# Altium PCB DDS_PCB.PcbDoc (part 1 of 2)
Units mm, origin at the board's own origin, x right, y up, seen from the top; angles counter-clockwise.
Board outline 101.55 x 88.3 mm, 8 copper layers (TOP_L1, Plane_L2, Inner_L3, Plane_L4, Plane_L5, Inner_L6, Plane_L7, Bottom Layer_L8), stack 0.681 mm thick; 434 components, 266 nets, 1385 pads, 24 vias.
Unrouted connection lines stored in the file: 977.
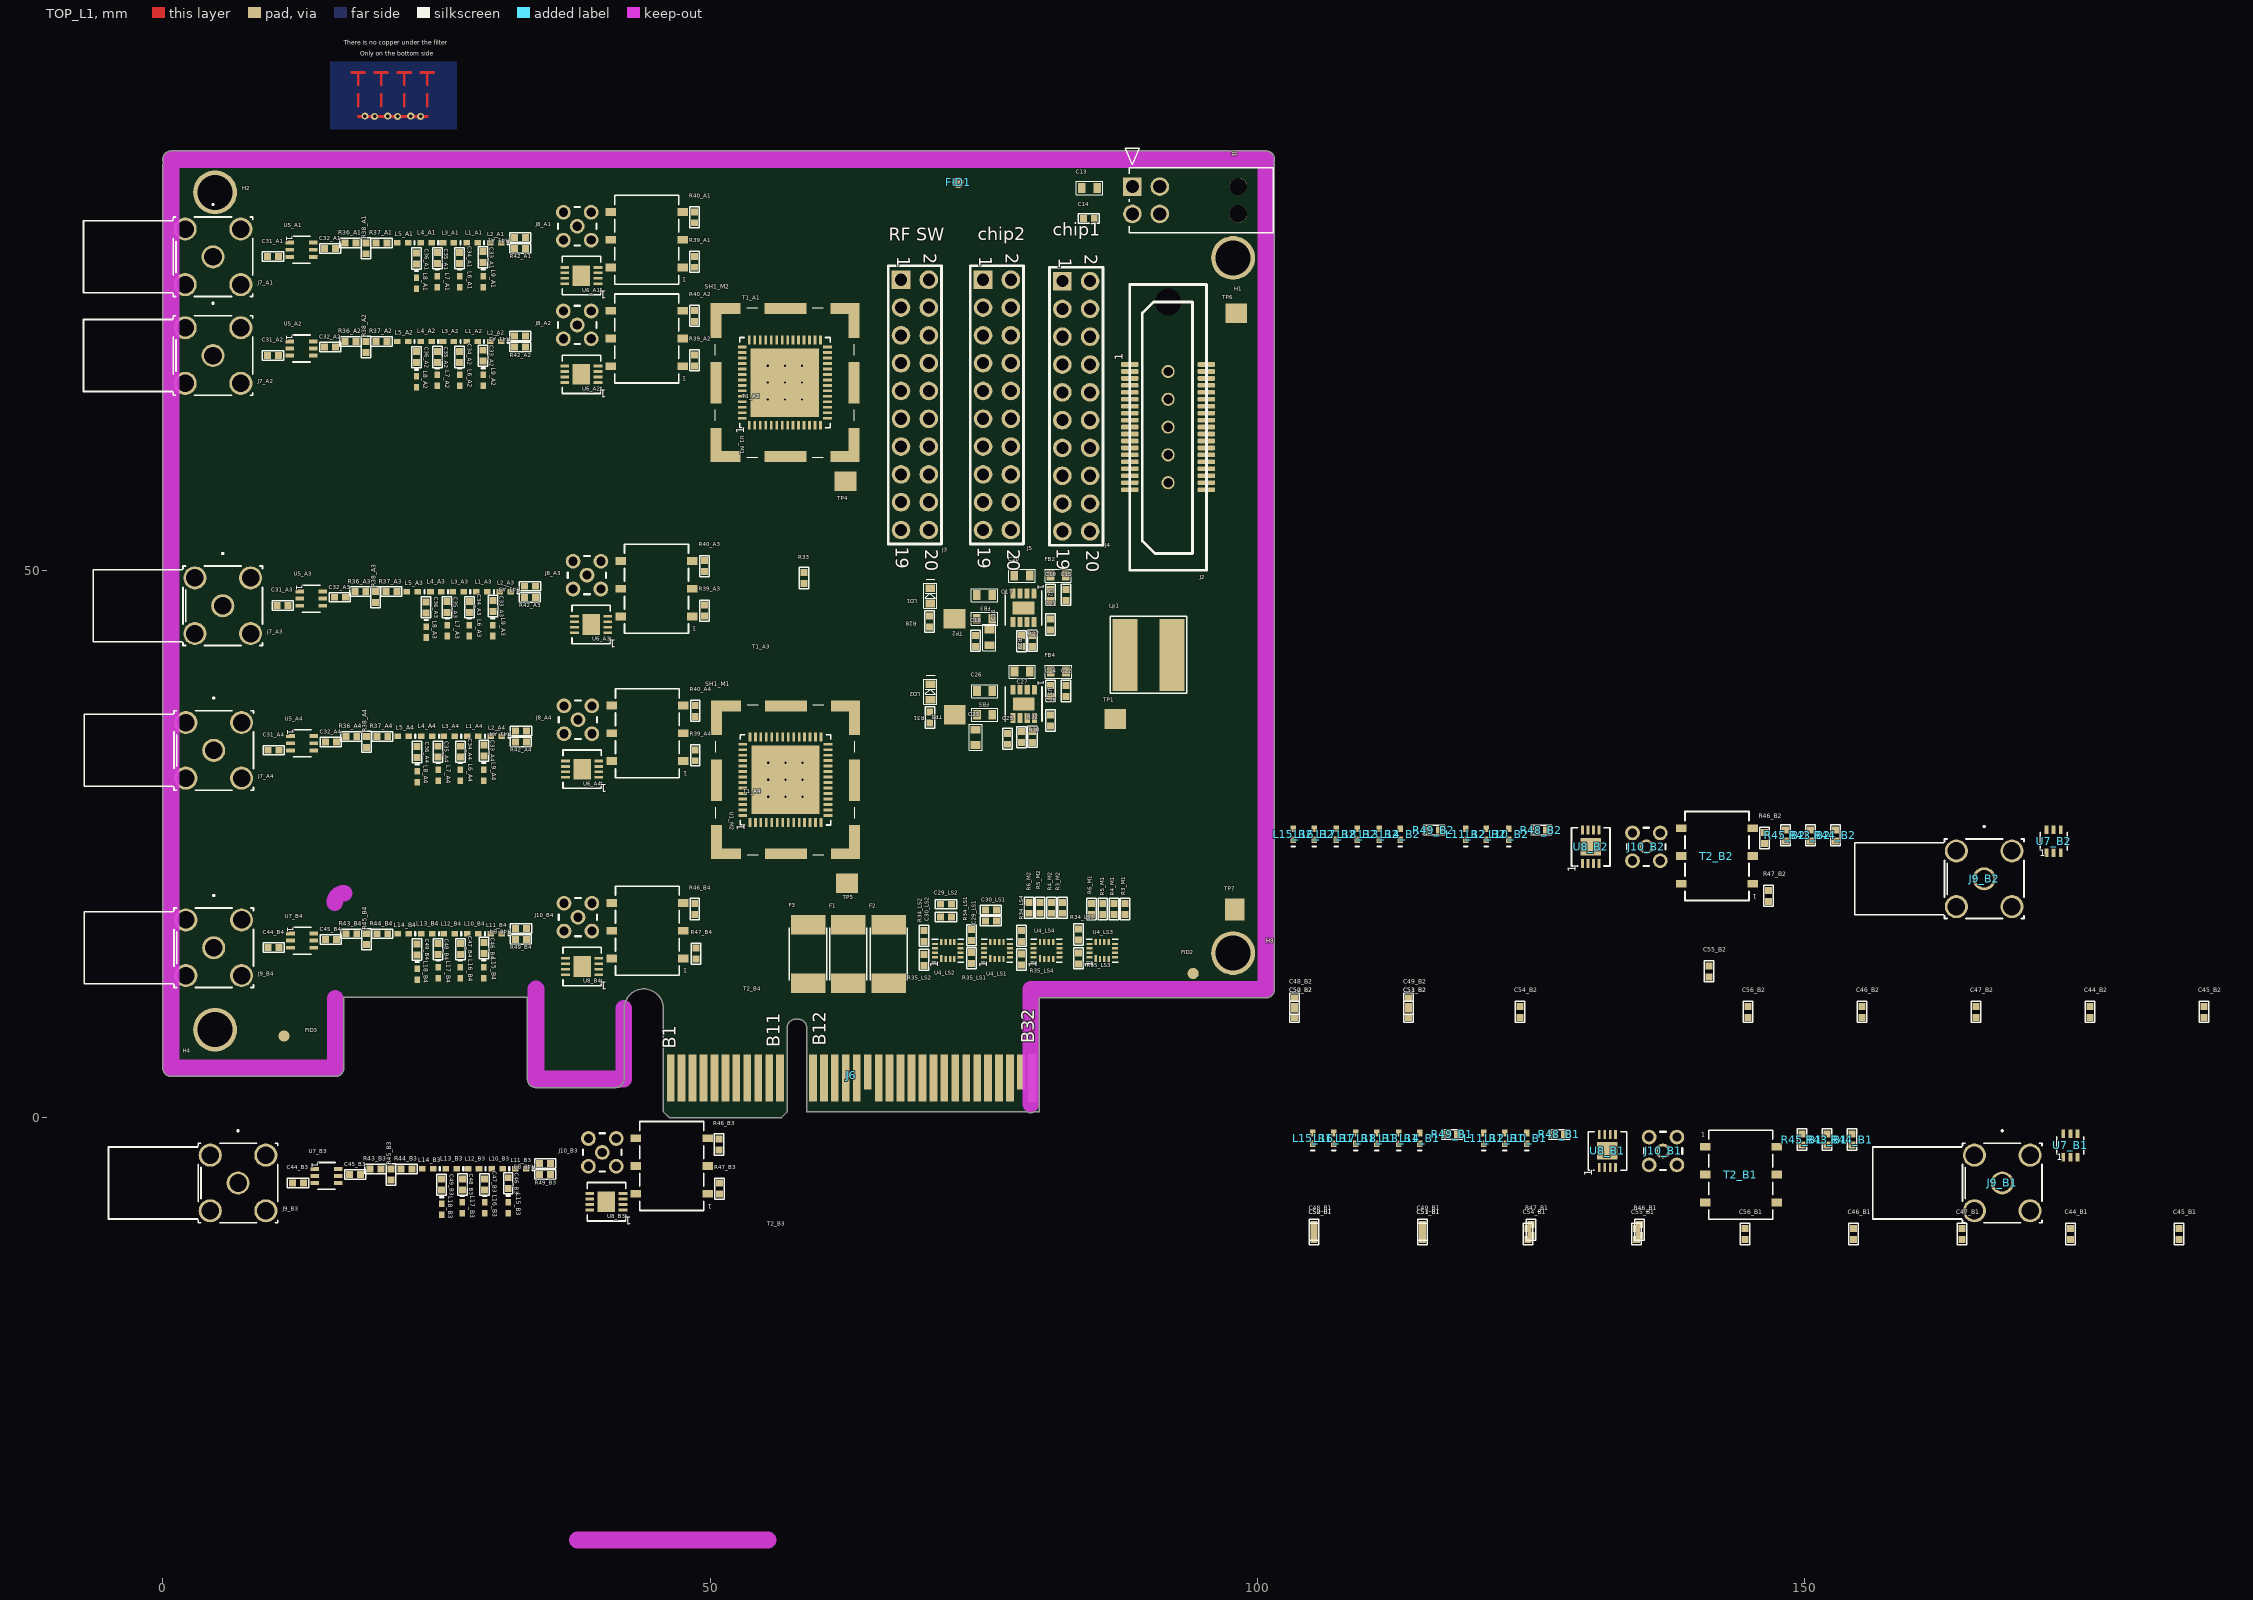
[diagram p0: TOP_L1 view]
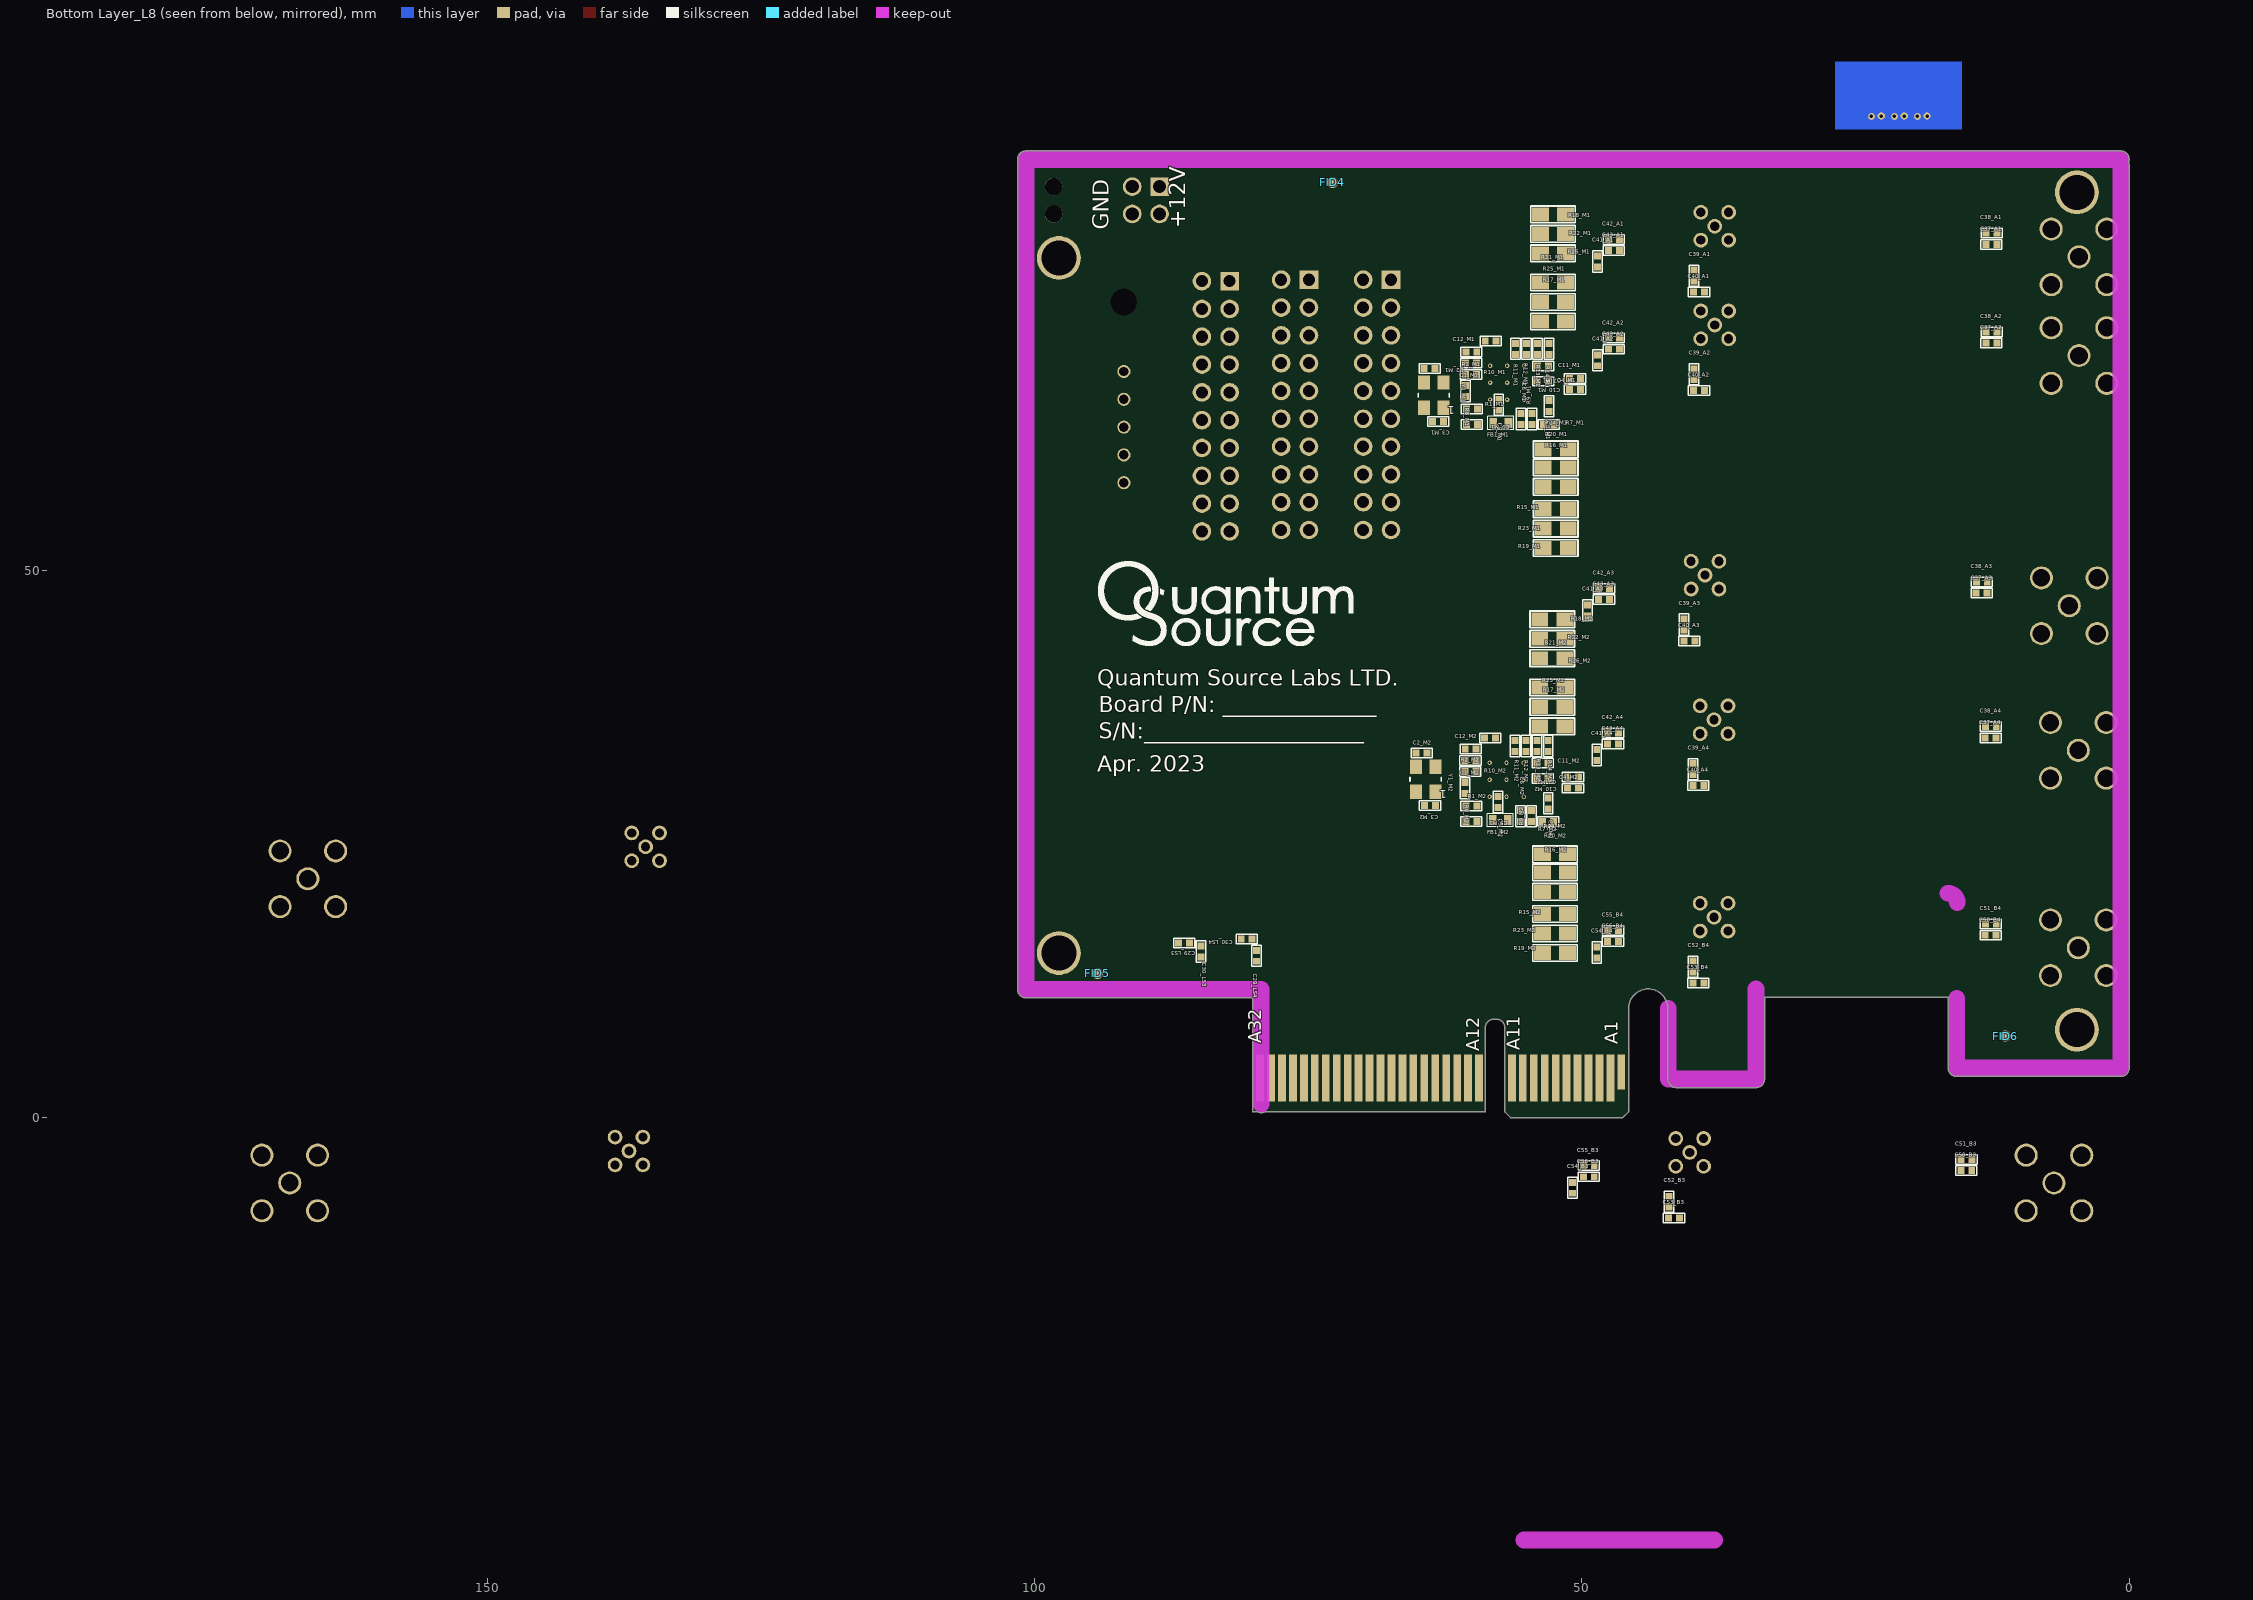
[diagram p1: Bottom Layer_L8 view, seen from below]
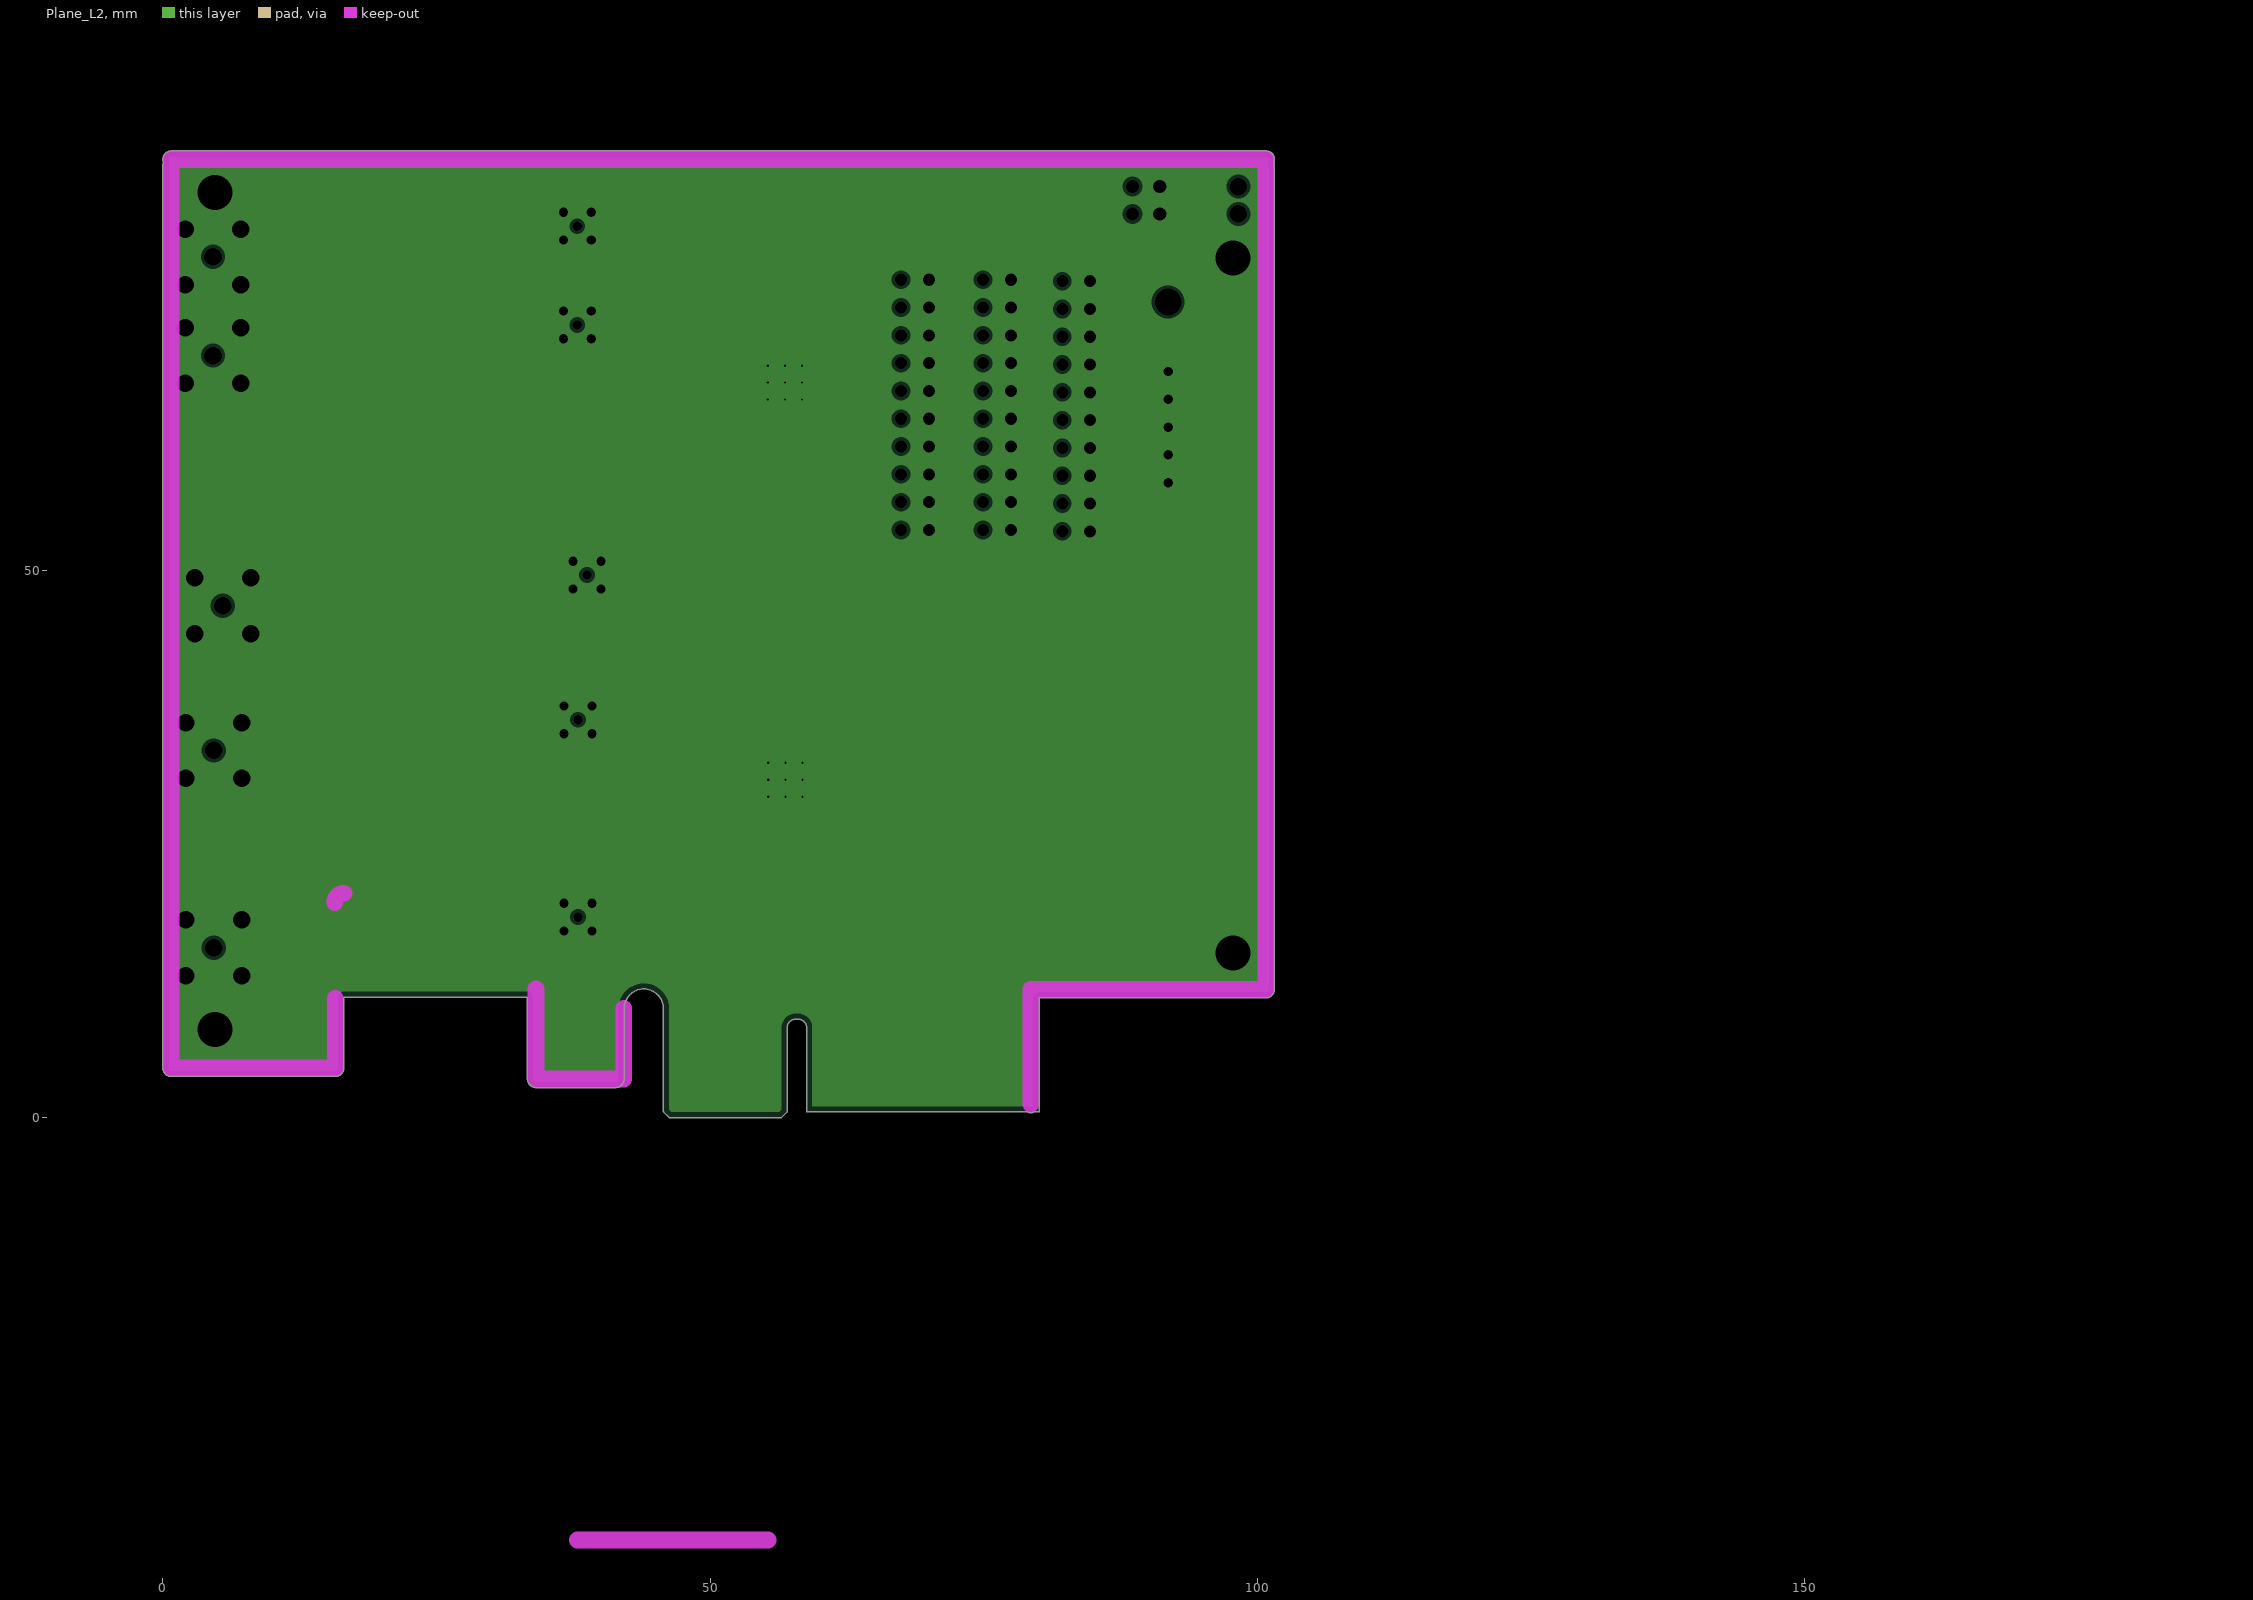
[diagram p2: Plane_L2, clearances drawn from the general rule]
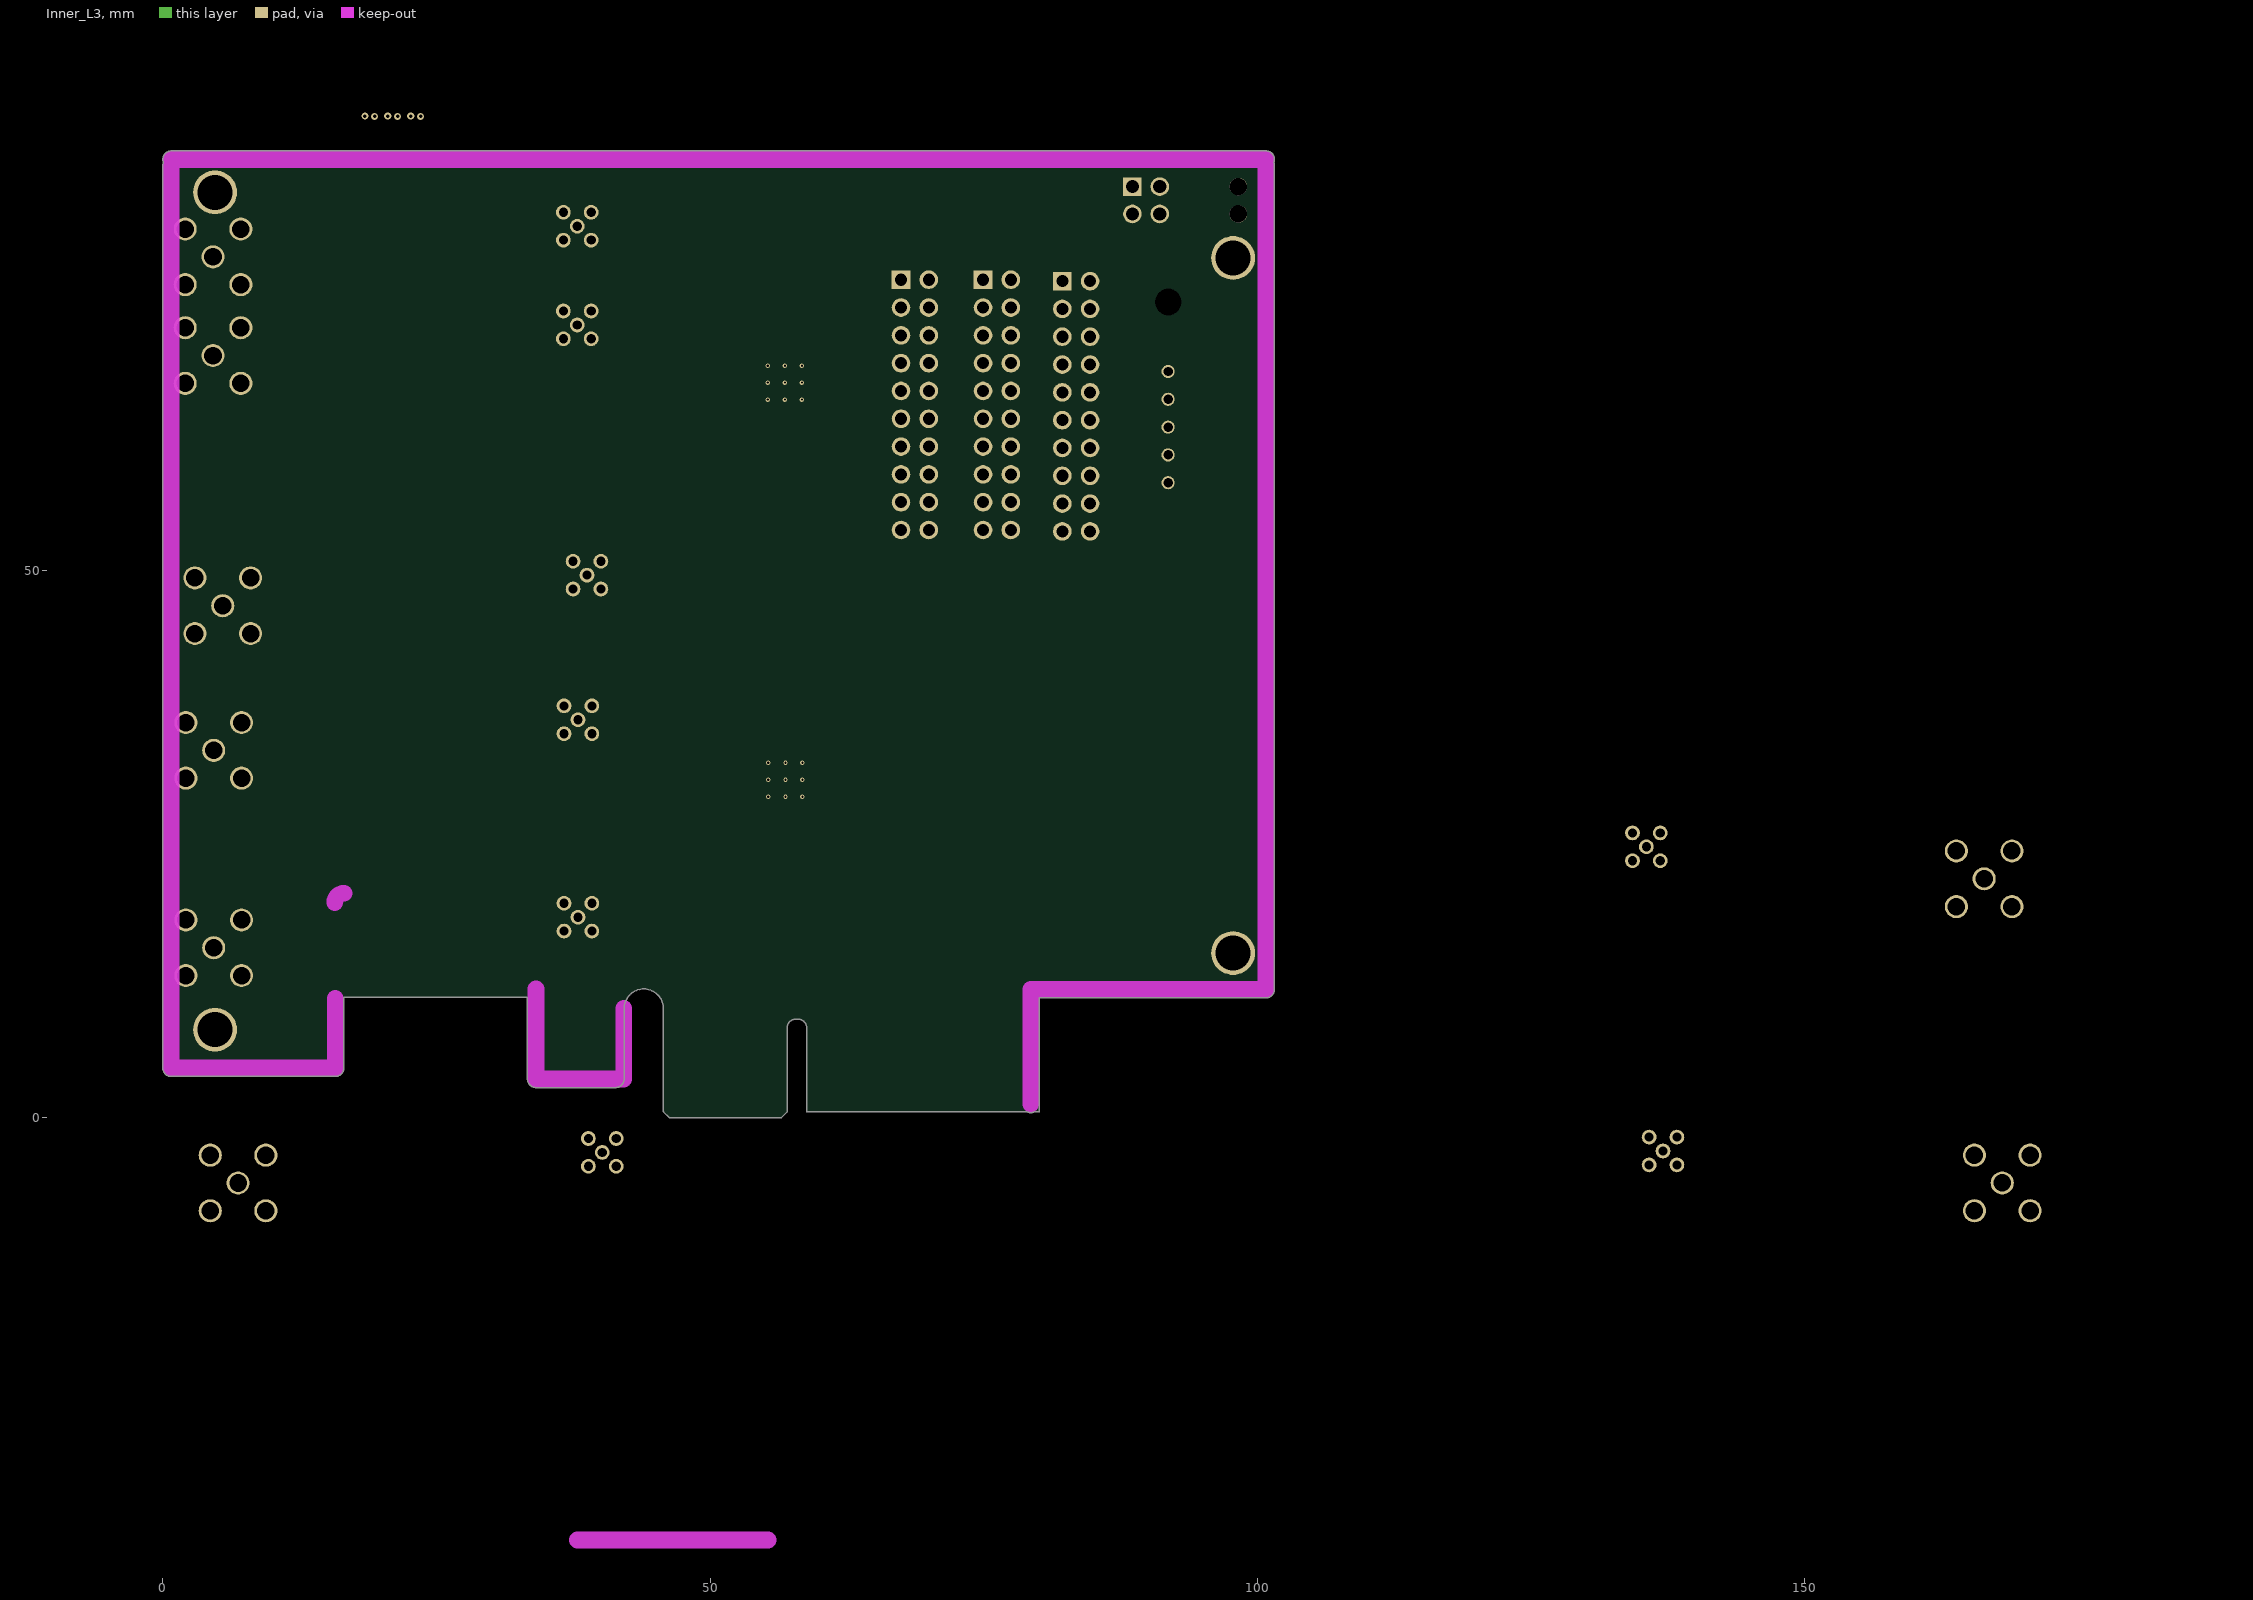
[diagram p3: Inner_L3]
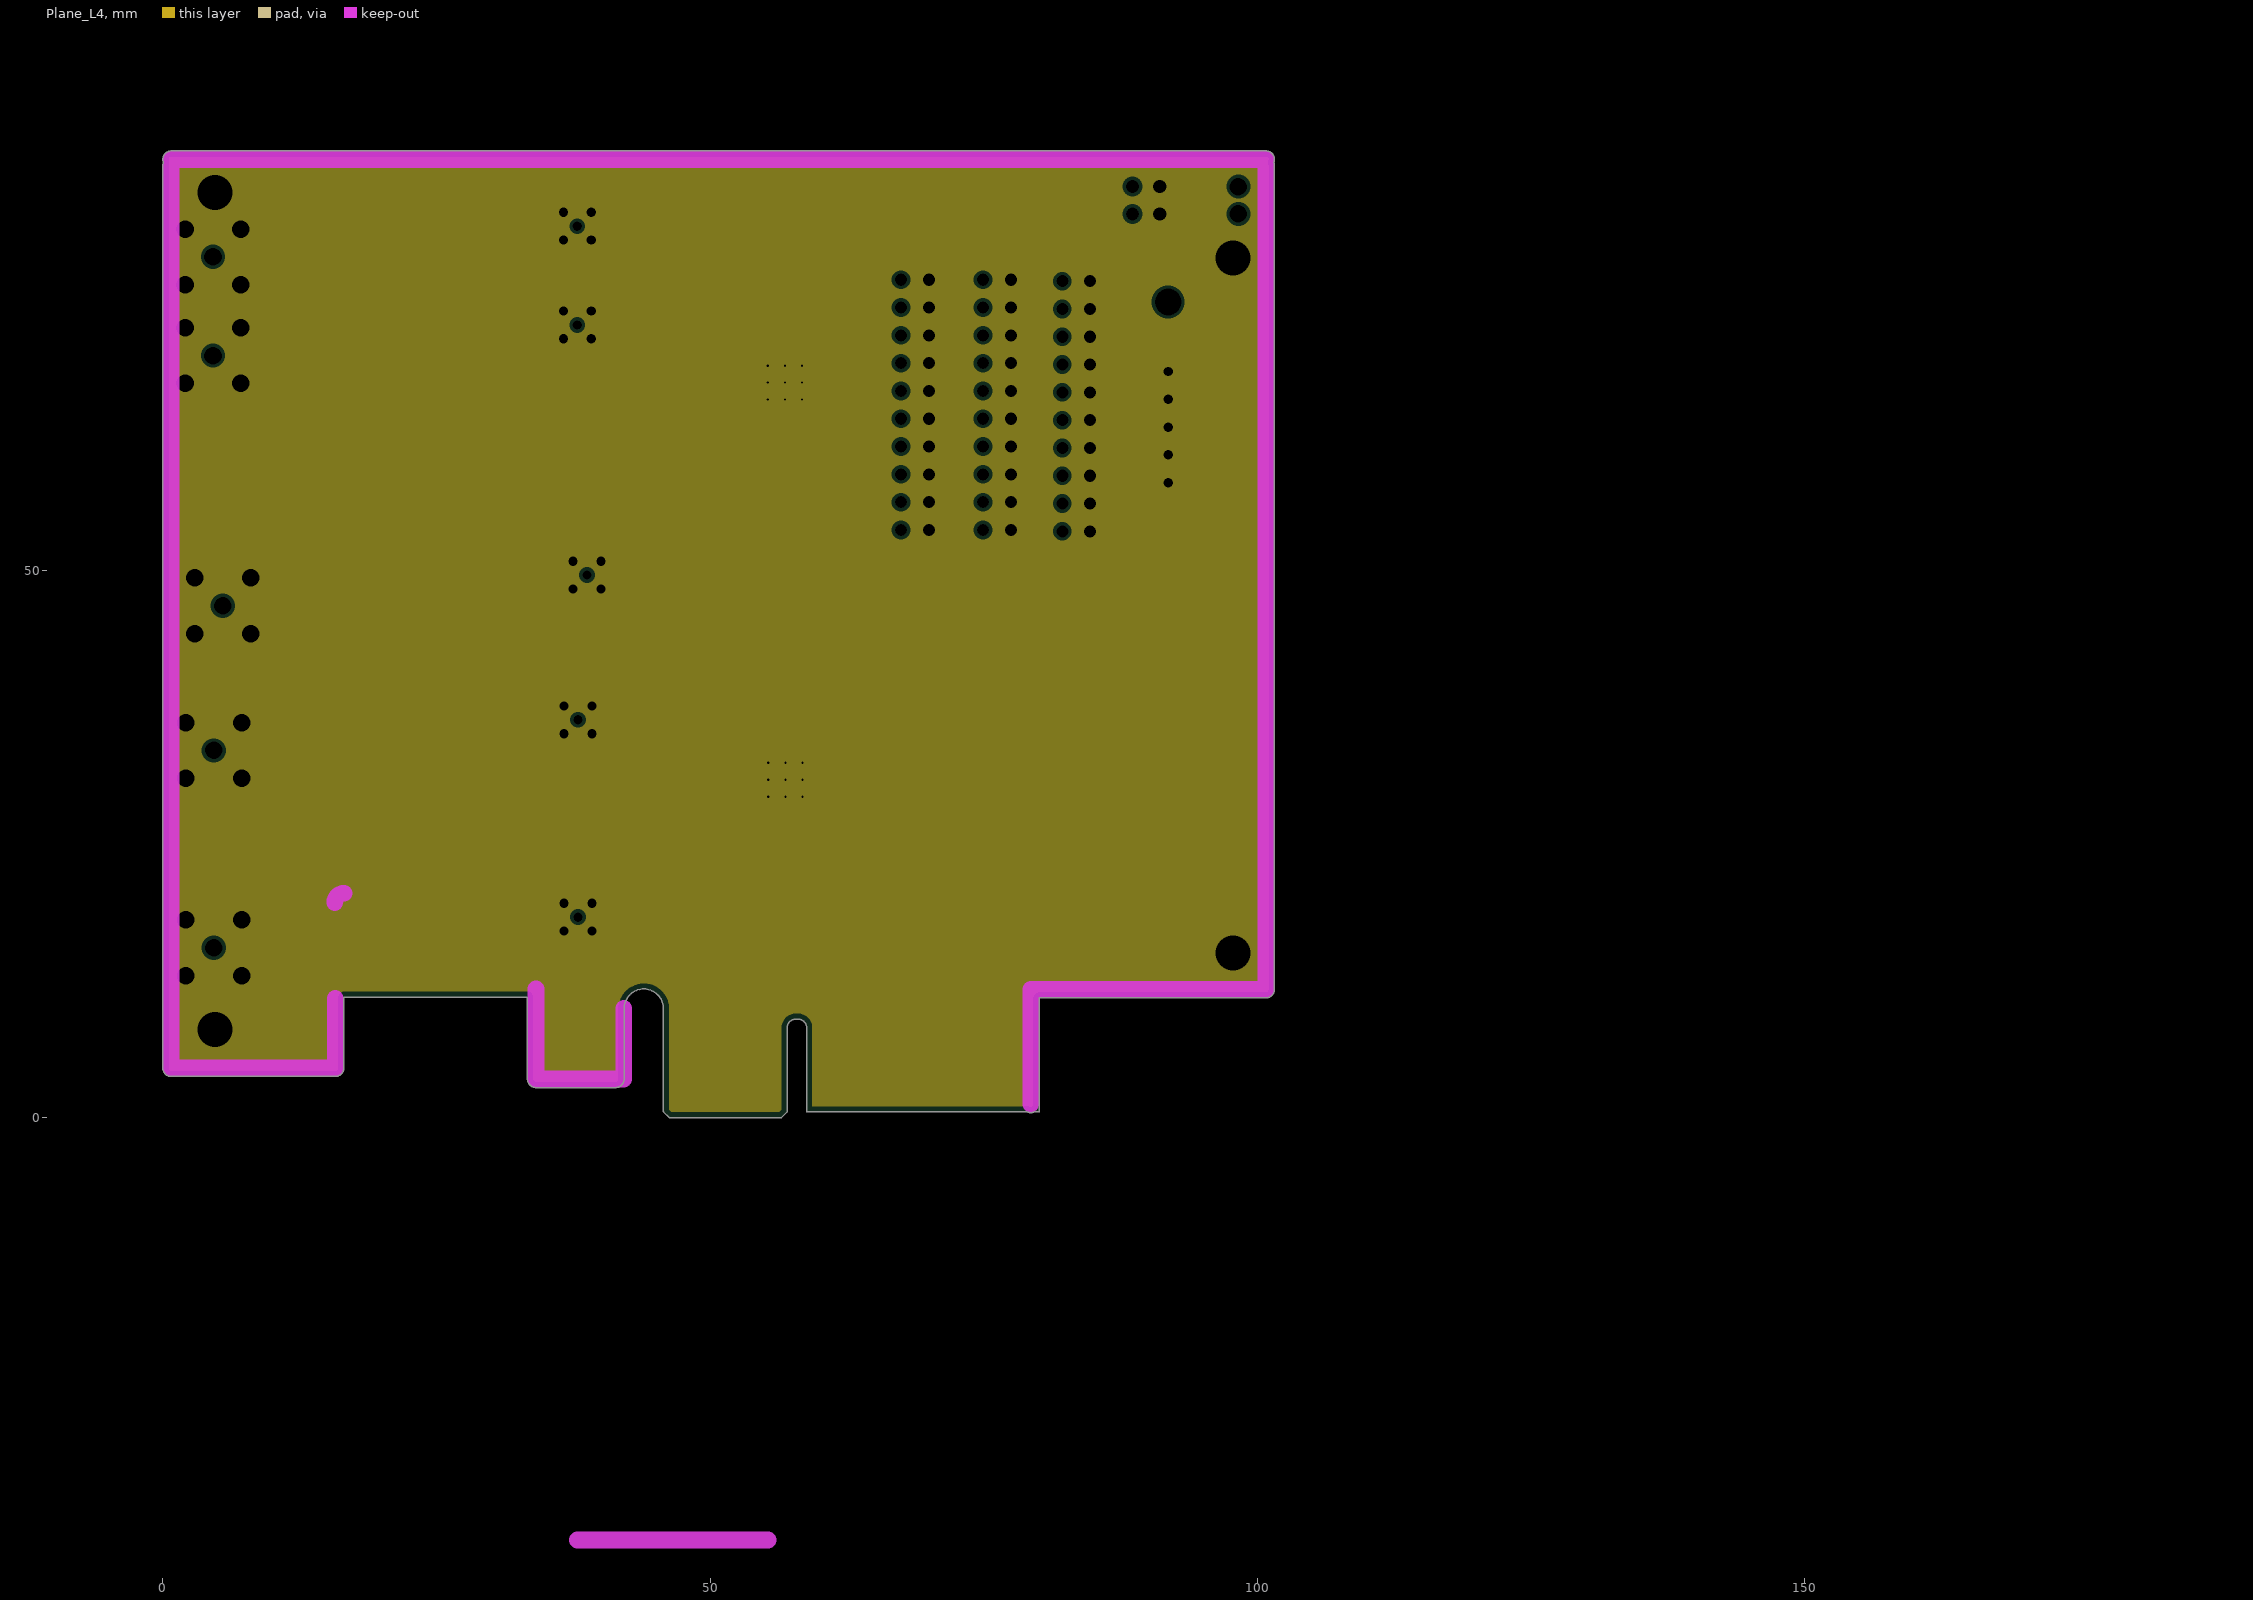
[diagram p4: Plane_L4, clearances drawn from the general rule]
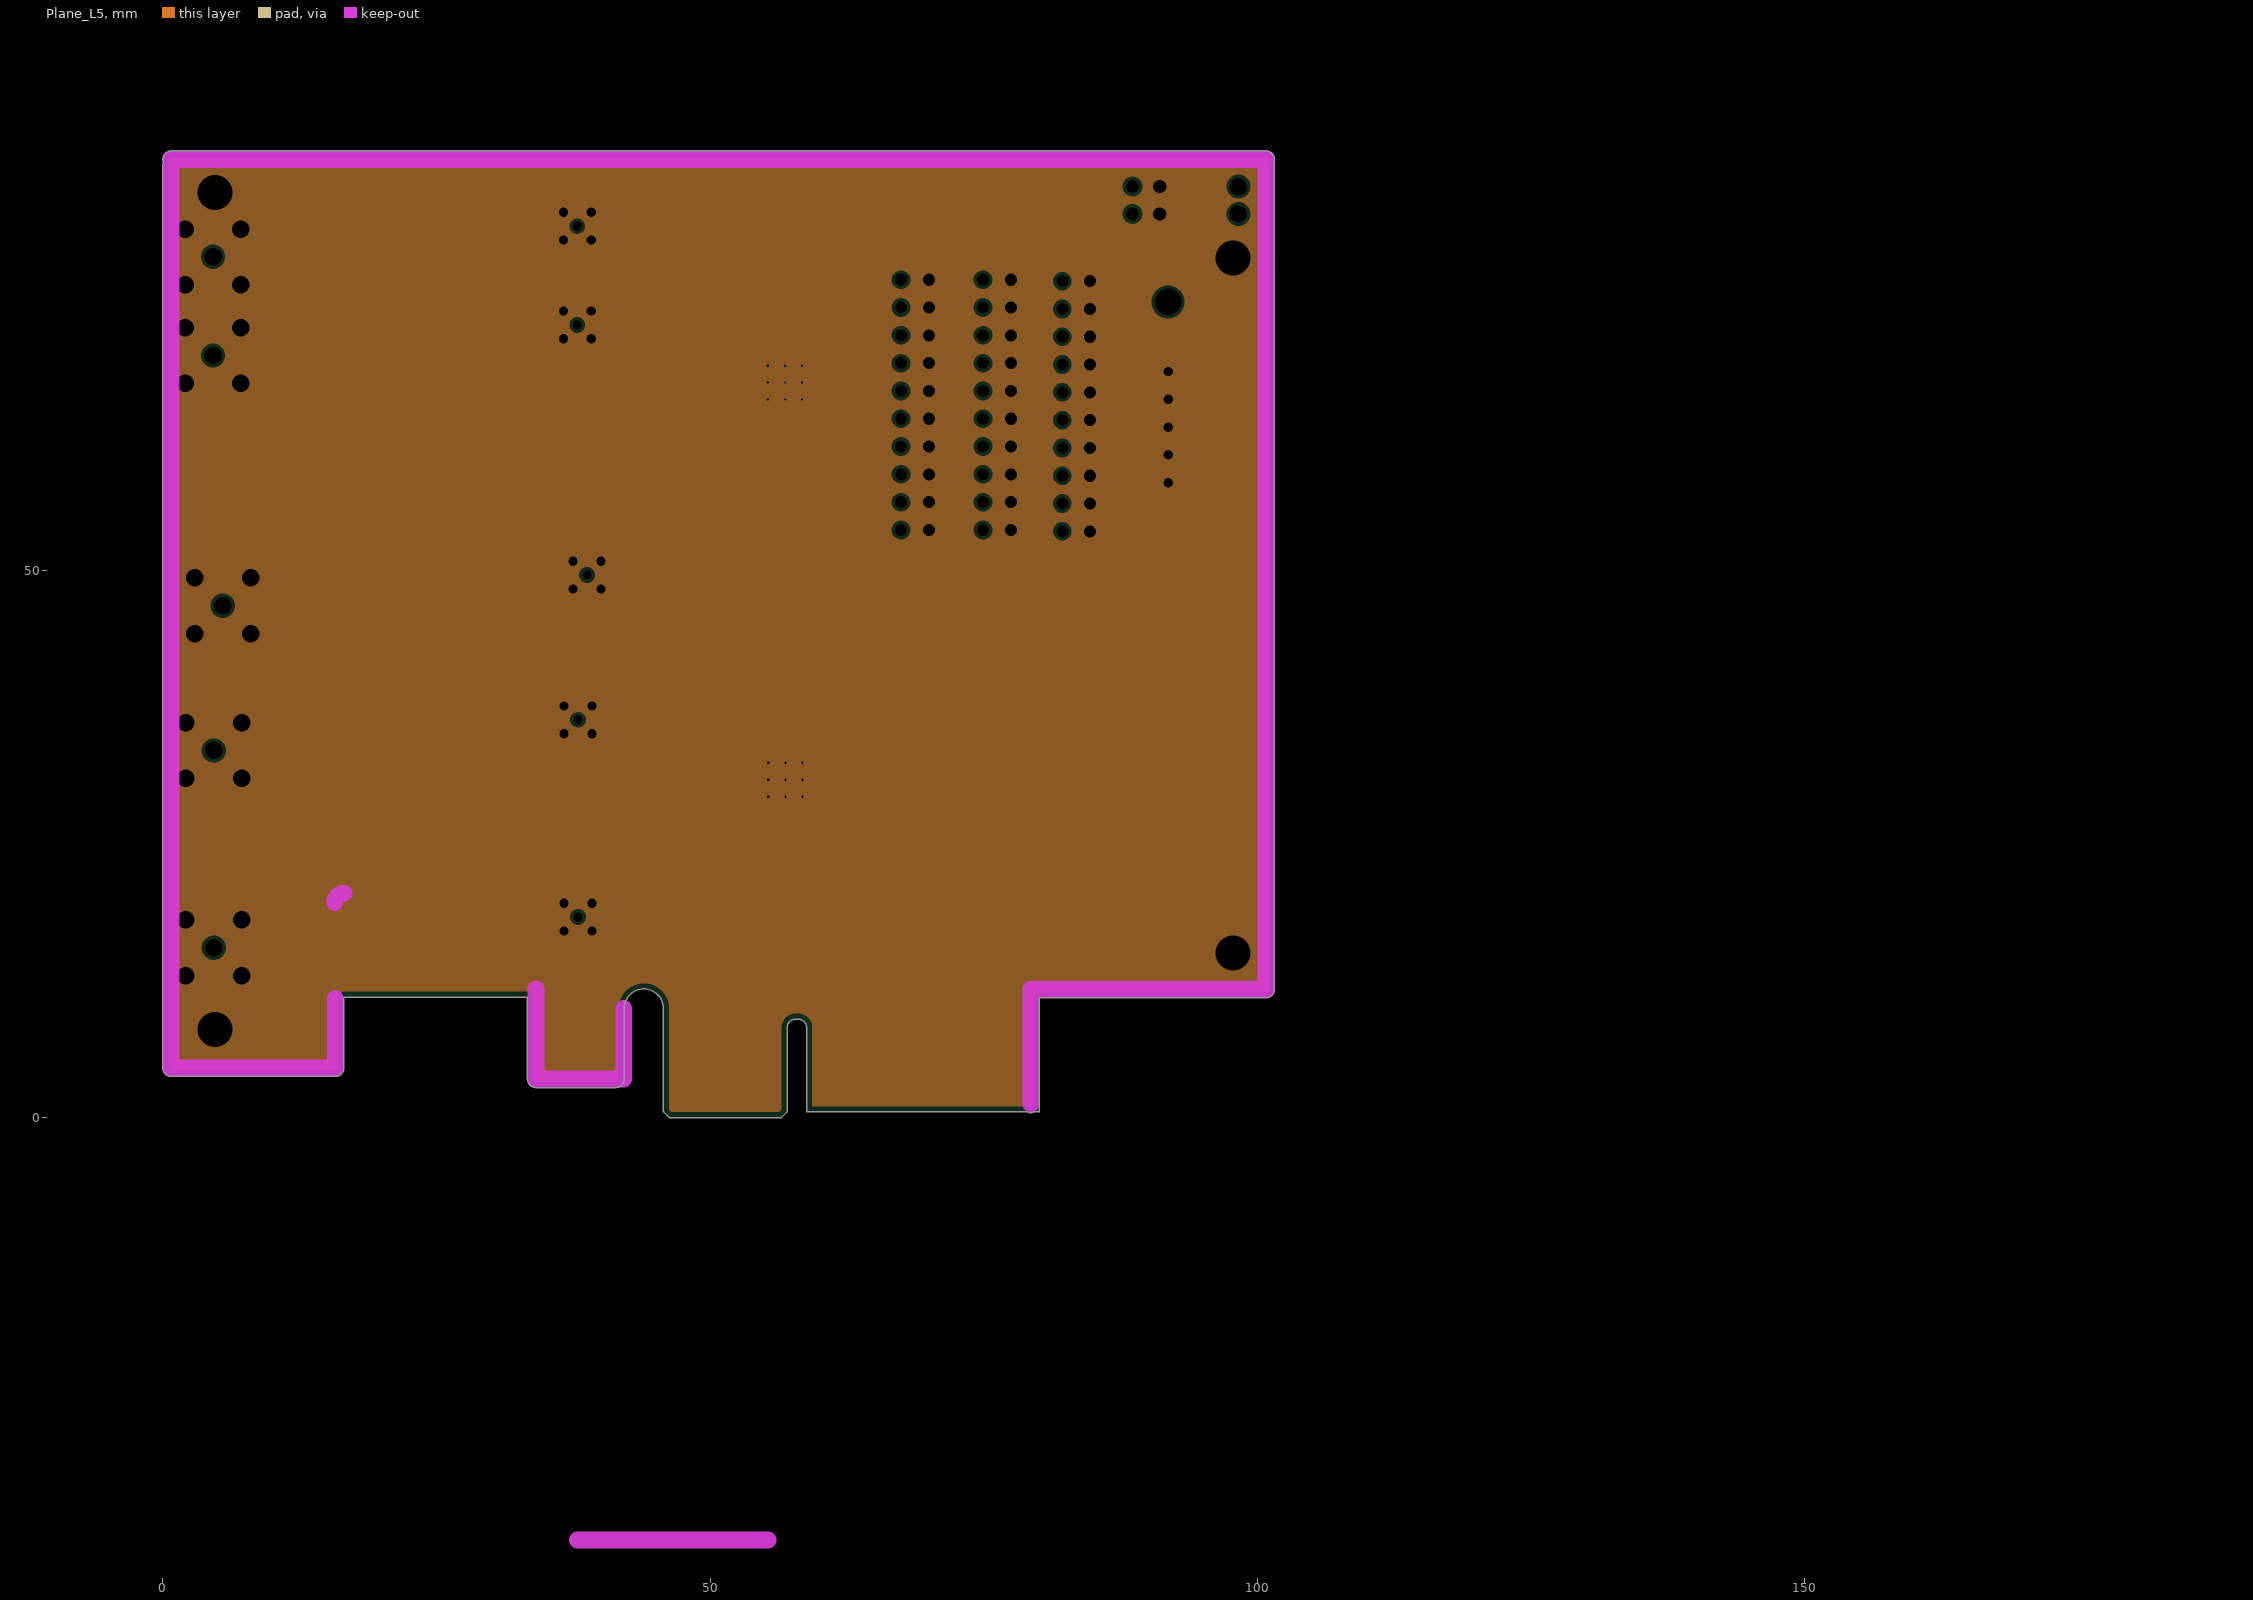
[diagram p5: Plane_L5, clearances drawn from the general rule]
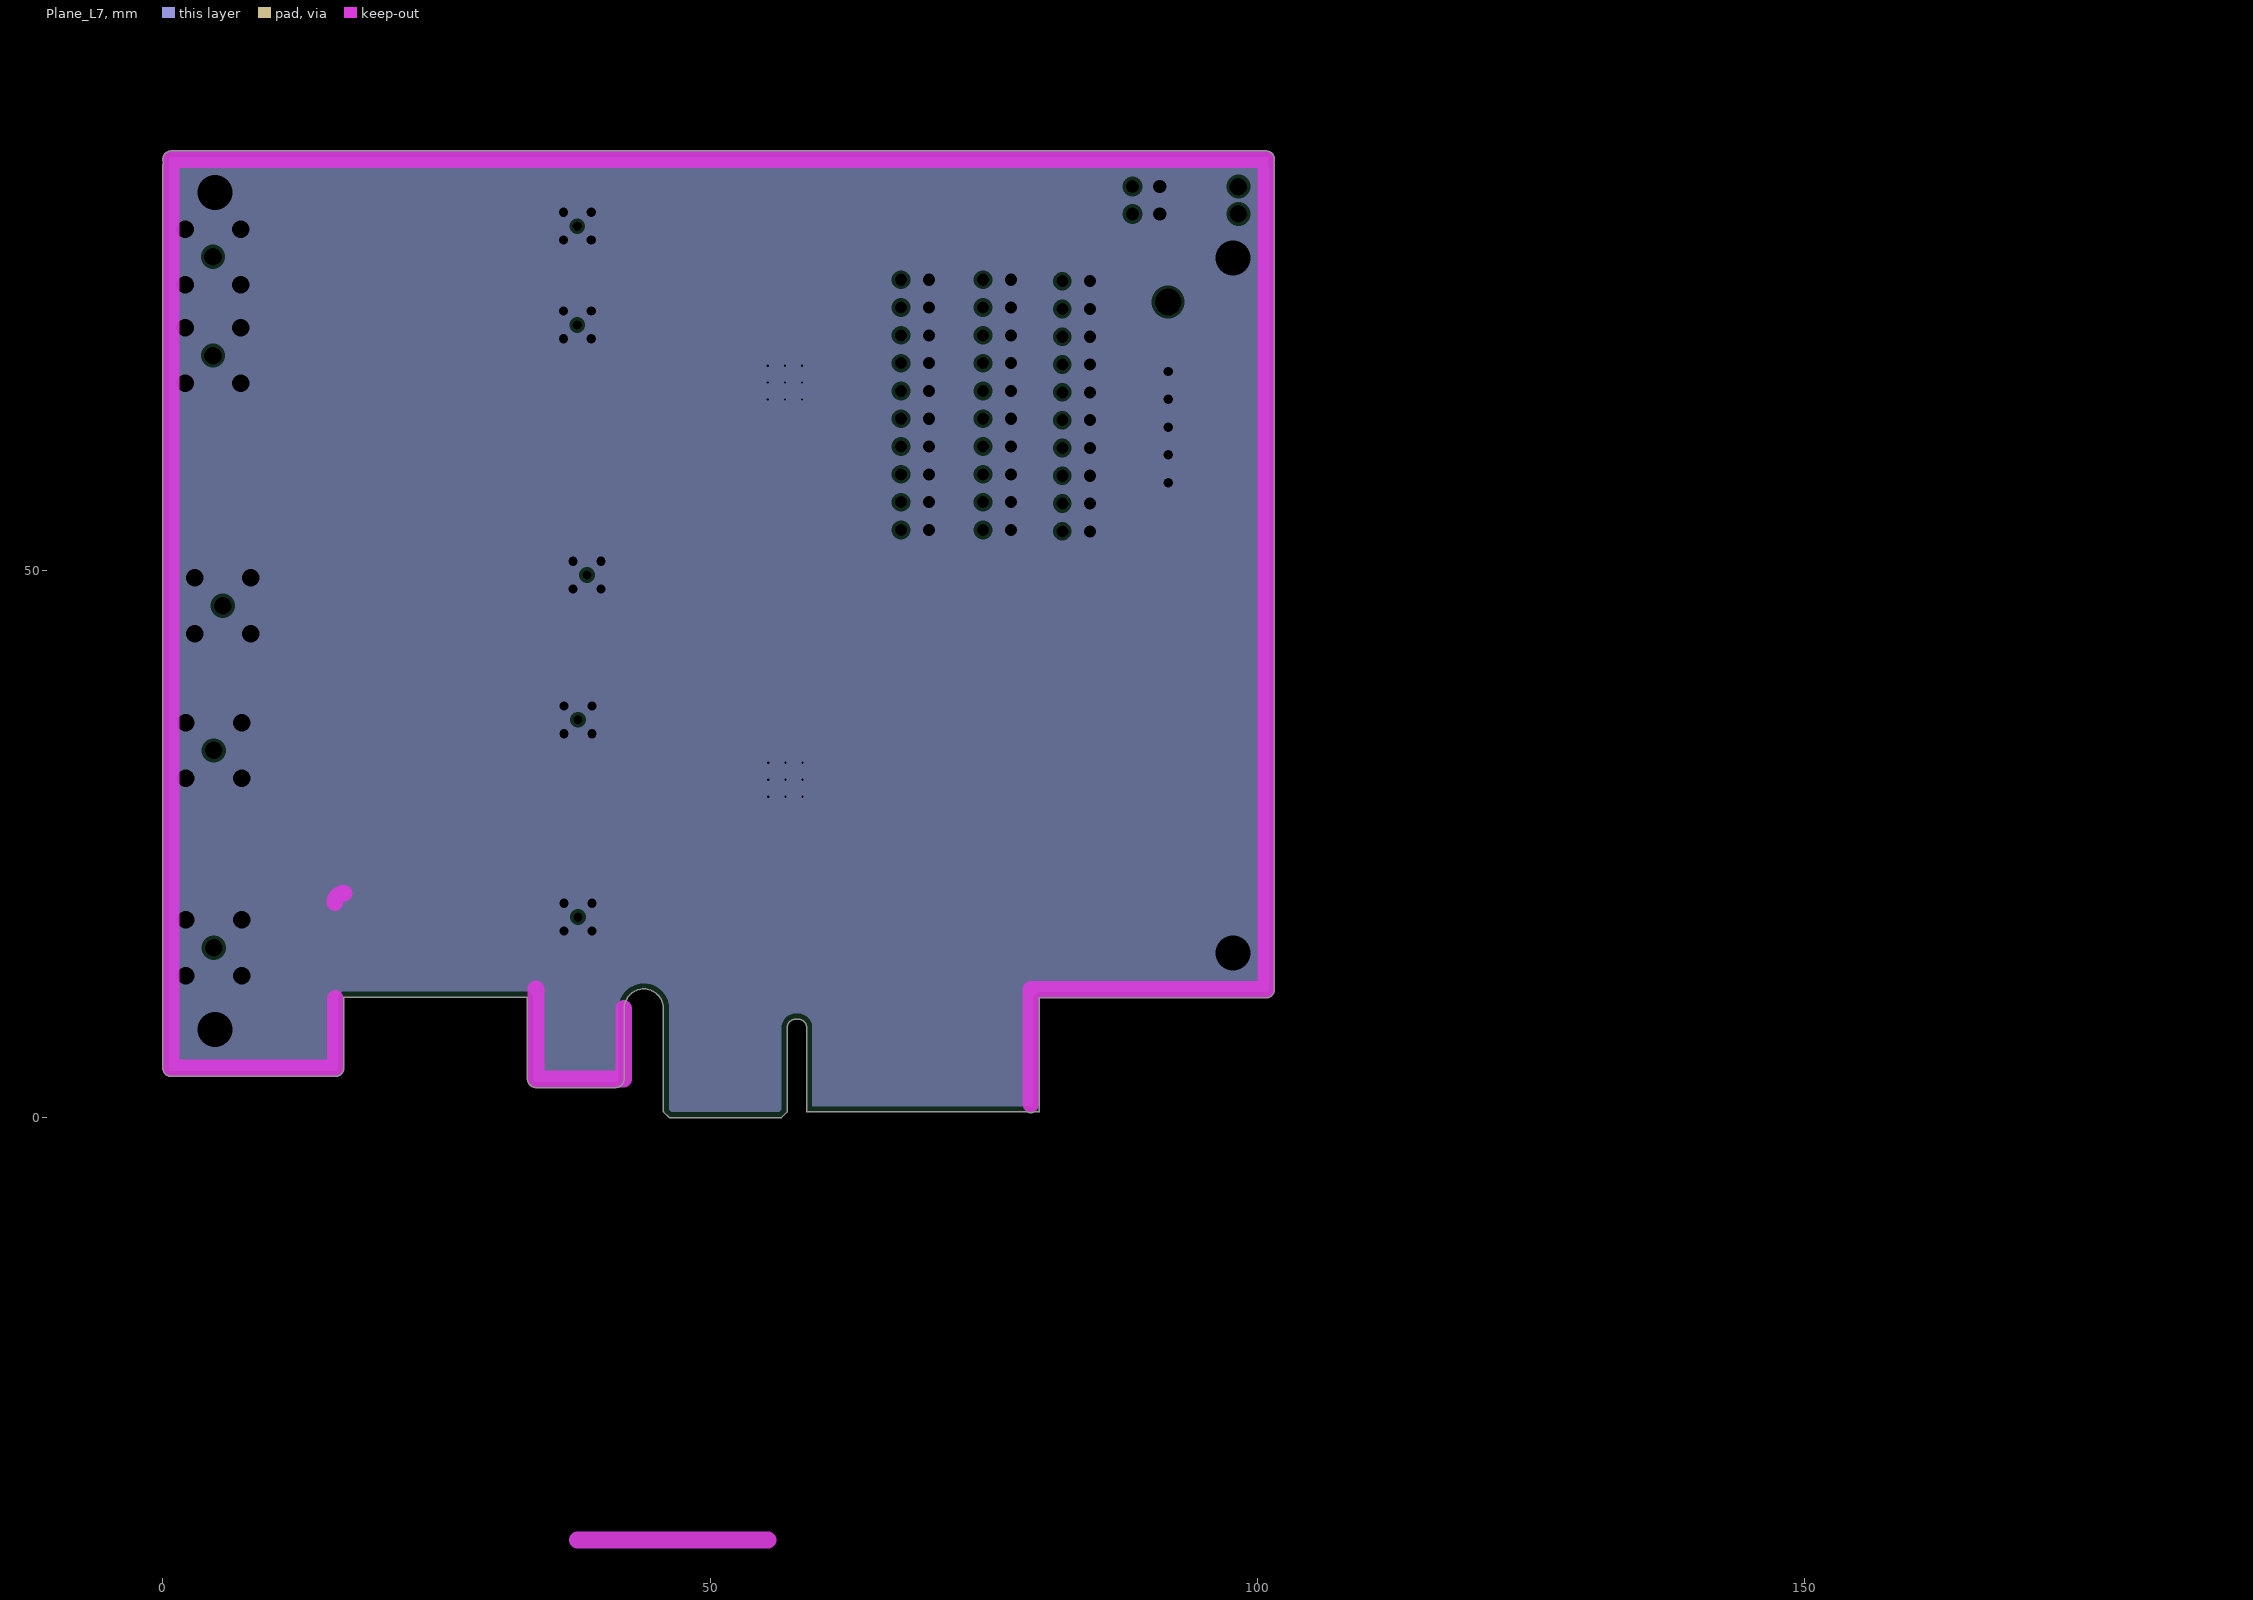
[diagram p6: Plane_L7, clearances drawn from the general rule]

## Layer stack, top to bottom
Top Solder: solder mask 0.0102, Solder Resist, Dk 3.5
TOP_L1: signal copper 0.0152
Dielectric1: core 0.0737, FR-4, Dk 3.2
Plane_L2: plane copper 0.0178, net GND
Dielectric7: prepreg 0.0762, FR-4, Dk 3.3
Inner_L3: signal copper 0.0178
Dielectric4: core 0.0711, FR-4, Dk 3.1
Plane_L4: plane copper 0.0305, net GND
Dielectric10: prepreg 0.0762, FR-4, Dk 3.3
Plane_L5: plane copper 0.0305, net GND
Dielectric 1: core 0.0711, FR-4, Dk 3.1
Inner_L6: signal copper 0.0178
Dielectric 6: prepreg 0.0762, FR-4, Dk 3.3
Plane_L7: plane copper 0.0178, net GND
Dielectric 7: core 0.0737, FR-4, Dk 3.2
Bottom Layer_L8: signal copper 0.0152
Board Layer Stack Bottom Solder: solder mask 0.0102, Solder Resist, Dk 3.5

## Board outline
0.762,3.734 cw(c0.762,4.509) -0.013,4.509 -0.013,86.932 cw(c0.762,86.932) 0.043,87.221 cw(c0.762,87.509) 0.762,88.285 100.762,88.285 cw(c100.762,87.509) 101.538,87.509 cw(c100.762,87.509) 101.482,87.221 cw(c100.762,86.932) 101.538,86.933 101.538,86.932 101.538,11.694 cw(c100.762,11.694) 100.762,10.919 80.053,10.919 80.053,0.522 80.026,0.496 79.569,0.496 cw(c79.264,1.209) 78.96,0.496 58.826,0.496 58.8,0.522 58.8,8.187 ccw(c58.009,8.187) 58.009,8.978 57.815,8.978 ccw(c57.815,8.183) 57.021,8.183 57.021,0.513 57.013,0.495 56.509,-0.009 56.491,-0.017 46.262,-0.017 46.244,-0.009 45.737,0.492 45.723,0.517 45.723,9.937 ccw(c43.927,9.937) 43.927,11.734 43.926,11.734 ccw(c43.926,9.959) 42.309,10.69 42.292,10.683 ccw(c43.926,9.937) 42.13,9.937 42.13,3.514 42.13,3.512 cw(c41.342,3.512) 41.342,2.724 34.087,2.724 cw(c34.087,3.512) 33.298,3.512 33.298,10.974 16.526,10.974 16.526,4.522 cw(c15.737,4.522) 15.737,3.734

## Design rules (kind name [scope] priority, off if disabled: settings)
Clearance [All] p1: gap=0.203 ignorepadtopadclearanceinfootprint=FALSE except(0: Arc-Hole Track-Hole SMDPad-Hole THPad-Hole Via-Hole Fill-Hole Poly-Hole Region-Hole Text-Hole)
DiffPairsRouting DiffPair_100OhmDiffPairsRouting [InDifferentialPairClass('New Class_100Ohm')] p1: maxlimit=0.165 minlimit=0.152 mostfreqgap=0.165 toplayer_maxgap=0.152 toplayer_prefgap=0.152 toplayer_minwidth=0.381 toplayer_maxwidth=0.381 toplayer_prefwidth=0.381 midlayer2_mingap=0.165 midlayer2_minwidth=0.381 midlayer2_maxwidth=0.381 midlayer2_prefwidth=0.381 midlayer4_mingap=0.165 midlayer4_minwidth=0.381 midlayer4_maxwidth=0.381 midlayer4_prefwidth=0.381 bottomlayer_maxgap=0.152 bottomlayer_prefgap=0.152 bottomlayer_minwidth=0.381 bottomlayer_maxwidth=0.381 bottomlayer_prefwidth=0.381 maxuncoupledlength=12.7
Length Length_GPIO2_[0..15] [InNetClass('GPIO2_[0..15]')] p1: maxlimit=41.351 minlimit=40.64
Length Length_DDR3_A0-15_control [InNetClass('DDR3_A[0..15]_CONTROL')] p2: maxlimit=60.985 minlimit=60.96
Length Length_SSF_TD1-6 [InDifferentialPairClass('New Class_SSF_TD1-6')] p3: maxlimit=268.707 minlimit=268.681
Length Length_PCI_RX0-7 [InDifferentialPairClass('New Class_PCI_RX0-6')] p4: maxlimit=66.065 minlimit=66.04
Length Length_PCI_TX0-7 [InDifferentialPairClass('New Class_PCI_TX0-6')] p5: maxlimit=51.206 minlimit=51.181
MatchedLengths DiffPair_85OhmMatchedLengths [All] p1: tolerance=0.635 checknetsindiffpair=TRUE checkdiffpairvsdiffpair=FALSE checkxsignals=FALSE checkothers=FALSE
MatchedLengths DiffPair_80OhmMatchedLengths [All] p2: tolerance=0.635 checknetsindiffpair=TRUE checkdiffpairvsdiffpair=FALSE checkxsignals=FALSE checkothers=FALSE
MatchedLengths DiffPair_100OhmMatchedLengths [All] p3: tolerance=0.635 checknetsindiffpair=TRUE checkdiffpairvsdiffpair=FALSE checkxsignals=FALSE checkothers=FALSE
PlaneClearance [All] p1: clearance=0.305
PlaneConnect PlaneConnect_Via [Isvia] p1: planeconnectstyle=Direct reliefexpansion=0.508 reliefentries=4 reliefconductorwidth=0.254 reliefairgap=0.254
PlaneConnect [All] p2: planeconnectstyle=Relief reliefexpansion=0.508 reliefentries=4 reliefconductorwidth=0.508 reliefairgap=0.203
PolygonConnect PolygonConnect_1PWRPAD [InPadClass('New Class_PWRpad')] p1: connectstyle=Direct reliefconductorwidth=0.254 reliefentries=4 polygonreliefangle="90 Angle" airgapwidth=0.254
PolygonConnect PolygonConnect_PWR [InComponentClass('New Class_pwr')] p2: connectstyle=Relief reliefconductorwidth=0.762 reliefentries=4 polygonreliefangle="90 Angle" airgapwidth=0.254
PolygonConnect PolygonConnect_Via [Isvia] p3: connectstyle=Direct reliefconductorwidth=0.254 reliefentries=4 polygonreliefangle="90 Angle" airgapwidth=0.254
PolygonConnect PolygonConnect_TPs [InComponentClass('New Class_TPs')] p4: connectstyle=Direct reliefconductorwidth=0.254 reliefentries=4 polygonreliefangle="90 Angle" airgapwidth=0.254
PolygonConnect [All] p5: connectstyle=Relief reliefconductorwidth=0.508 reliefentries=4 polygonreliefangle="90 Angle" airgapwidth=0.254
RoomDefinition A4 [InComponentClass('A4')] p1: confinementstyle=ConfineIn formatcopy=TRUE lockcomponents=FALSE outline -7.62,29.16 49.403,29.16 49.403,39.574 -7.62,39.574
RoomDefinition B3 [InComponentClass('B3')] p2: confinementstyle=ConfineIn formatcopy=TRUE lockcomponents=FALSE outline -5.397,-10.363 51.626,-10.363 51.626,0.051 -5.397,0.051
RoomDefinition A1 [InComponentClass('A1')] p3: confinementstyle=ConfineIn formatcopy=TRUE lockcomponents=FALSE outline -7.62,74.245 49.403,74.245 49.403,84.659 -7.62,84.659
RoomDefinition A2 [InComponentClass('A2')] p4: confinementstyle=ConfineIn formatcopy=TRUE lockcomponents=FALSE outline -7.62,65.228 49.403,65.228 49.403,75.642 -7.62,75.642
RoomDefinition B4 [InComponentClass('B4')] p5: confinementstyle=ConfineIn formatcopy=TRUE lockcomponents=FALSE outline -7.62,11.126 49.53,11.126 49.53,21.54 -7.62,21.54
RoomDefinition B1 [InComponentClass('B1')] p6: confinementstyle=ConfineIn formatcopy=TRUE lockcomponents=FALSE outline 104.394,-10.056 175.895,-10.056 175.895,-0.658 104.394,-0.658
RoomDefinition A3 [InComponentClass('A3')] p7: confinementstyle=ConfineIn formatcopy=TRUE lockcomponents=FALSE outline -6.731,42.652 50.292,42.652 50.292,52.812 -6.731,52.812
RoomDefinition B2 [InComponentClass('B2')] p8: confinementstyle=ConfineIn formatcopy=TRUE lockcomponents=FALSE outline -7.62,65.228 49.403,65.228 49.403,75.642 -7.62,75.642
RoutingVias [All] p1: holewidth=0.254 width=0.508 viastyle="Through Hole" minholewidth=0.254 minwidth=0.508 maxholewidth=0.711 maxwidth=1.27
SilkToSolderMaskClearance SilkscreenOverComponentPads [IsPad] p1: minsilkscreentomaskgap=0.254 clearancetoexposedcopper=TRUE
SolderMaskExpansion [All] p1: expansion=0.102 istentingtop=FALSE
Width [All] p1: maxlimit=2.54 minlimit=0.152 preferedwidth=0.203
26 further rules are at their usual default settings.

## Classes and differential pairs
component class B4: C44_B4 C45_B4 C46_B4 C47_B4 C48_B4 C49_B4 C50_B4 C51_B4 C52_B4 C53_B4 C54_B4 C55_B4 C56_B4 J9_B4 J10_B4 L10_B4 L11_B4 L12_B4 L13_B4 L14_B4 L15_B4 L16_B4 L17_B4 L18_B4 R43_B4 R44_B4 R45_B4 R46_B4 R47_B4 R48_B4 R49_B4 T2_B4 U7_B4 U8_B4
component class B2: C44_B2 C45_B2 C46_B2 C47_B2 C48_B2 C49_B2 C50_B2 C51_B2 C52_B2 C53_B2 C54_B2 C55_B2 C56_B2 J9_B2 J10_B2 L10_B2 L11_B2 L12_B2 L13_B2 L14_B2 L15_B2 L16_B2 L17_B2 L18_B2 R43_B2 R44_B2 R45_B2 R46_B2 R47_B2 R48_B2 R49_B2 T2_B2 U7_B2 U8_B2
component class B1: C44_B1 C45_B1 C46_B1 C47_B1 C48_B1 C49_B1 C50_B1 C51_B1 C52_B1 C53_B1 C54_B1 C55_B1 C56_B1 J9_B1 J10_B1 L10_B1 L11_B1 L12_B1 L13_B1 L14_B1 L15_B1 L16_B1 L17_B1 L18_B1 R43_B1 R44_B1 R45_B1 R46_B1 R47_B1 R48_B1 R49_B1 T2_B1 U7_B1 U8_B1
component class A3: C31_A3 C32_A3 C33_A3 C34_A3 C35_A3 C36_A3 C37_A3 C38_A3 C39_A3 C40_A3 C41_A3 C42_A3 C43_A3 J7_A3 J8_A3 L1_A3 L2_A3 L3_A3 L4_A3 L5_A3 L6_A3 L7_A3 L8_A3 L9_A3 R36_A3 R37_A3 R38_A3 R39_A3 R40_A3 R41_A3 R42_A3 T1_A3 U5_A3 U6_A3
channel class analog_channel3: B1 B2 B3 B4
component class A4: C31_A4 C32_A4 C33_A4 C34_A4 C35_A4 C36_A4 C37_A4 C38_A4 C39_A4 C40_A4 C41_A4 C42_A4 C43_A4 J7_A4 J8_A4 L1_A4 L2_A4 L3_A4 L4_A4 L5_A4 L6_A4 L7_A4 L8_A4 L9_A4 R36_A4 R37_A4 R38_A4 R39_A4 R40_A4 R41_A4 R42_A4 T1_A4 U5_A4 U6_A4
component class B3: C44_B3 C45_B3 C46_B3 C47_B3 C48_B3 C49_B3 C50_B3 C51_B3 C52_B3 C53_B3 C54_B3 C55_B3 C56_B3 J9_B3 J10_B3 L10_B3 L11_B3 L12_B3 L13_B3 L14_B3 L15_B3 L16_B3 L17_B3 L18_B3 R43_B3 R44_B3 R45_B3 R46_B3 R47_B3 R48_B3 R49_B3 T2_B3 U7_B3 U8_B3
component class A2: C31_A2 C32_A2 C33_A2 C34_A2 C35_A2 C36_A2 C37_A2 C38_A2 C39_A2 C40_A2 C41_A2 C42_A2 C43_A2 J7_A2 J8_A2 L1_A2 L2_A2 L3_A2 L4_A2 L5_A2 L6_A2 L7_A2 L8_A2 L9_A2 R36_A2 R37_A2 R38_A2 R39_A2 R40_A2 R41_A2 R42_A2 T1_A2 U5_A2 U6_A2
component class A1: C31_A1 C32_A1 C33_A1 C34_A1 C35_A1 C36_A1 C37_A1 C38_A1 C39_A1 C40_A1 C41_A1 C42_A1 C43_A1 J7_A1 J8_A1 L1_A1 L2_A1 L3_A1 L4_A1 L5_A1 L6_A1 L7_A1 L8_A1 L9_A1 R36_A1 R37_A1 R38_A1 R39_A1 R40_A1 R41_A1 R42_A1 T1_A1 U5_A1 U6_A1
channel class analog_channel: A1 A2 A3 A4
channel class "Level Shifter": LS1 LS2 LS3 LS4
channel class main: M1 M2
differential pair CH_B4: +CH_B4_P -CH_B4_N
differential pair CH_B3: +CH_B3_P -CH_B3_N
differential pair CH_B2: +CH_B2_P -CH_B2_N
differential pair CH_B1: +CH_B1_P -CH_B1_N
differential pair CH3_M2: +CH_P3_M2 -CH_N3_M2
differential pair CH3_M1: +CH_P3_M1 -CH_N3_M1
differential pair CH2_M2: +CH_P2_M2 -CH_N2_M2
differential pair CH2_M1: +CH_P2_M1 -CH_N2_M1
differential pair CH1_M2: +CH_P1_M2 -CH_N1_M2
differential pair CH1_M1: +CH_P1_M1 -CH_N1_M1
differential pair CH0_M2: +CH_P0_M2 -CH_N0_M2
differential pair CH0_M1: +CH_P0_M1 -CH_N0_M1

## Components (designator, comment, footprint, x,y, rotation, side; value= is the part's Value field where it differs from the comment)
C1_M1 "680pF 50V" C0402 60.141,68.898 r180 bottom (schematic designator C1)
C1_M2 "680pF 50V" C0402 60.193,32.616 r180 bottom (schematic designator C1)
C2_M1 "39pF 50V" C0402 63.918,68.39 r180 bottom (schematic designator C2)
C2_M2 "39pF 50V" C0402 64.664,33.306 r180 bottom (schematic designator C2)
C3_M1 "39pF 50V" C0402 63.156,63.564 r180 bottom (schematic designator C3)
C3_M2 "39pF 50V" C0402 63.902,28.48 r180 bottom (schematic designator C3)
C4_M1 "1uF 25V" C0402 53.552,67.247 r180 bottom (schematic designator C4)
C4_M2 "1uF 25V" C0402 53.604,30.965 r180 bottom (schematic designator C4)
C5_M1 "1uF 25V" C0402 57.578,65.126 r270 bottom (schematic designator C5)
C5_M2 "1uF 25V" C0402 57.63,28.845 r270 bottom (schematic designator C5)
C6_M1 "1uF 25V" C0402 55.546,63.841 r270 bottom (schematic designator C6)
C6_M2 "1uF 25V" C0402 55.598,27.559 r270 bottom (schematic designator C6)
C7_M1 "10uF 10V" C0402 50.571,67.501 r0 bottom (schematic designator C7)
C7_M2 "10uF 10V" C0402 50.762,31.084 r0 bottom (schematic designator C7)
C8_M1 "10uF 10V" C0402 53.006,64.999 r270 bottom (schematic designator C8)
C8_M2 "10uF 10V" C0402 53.058,28.718 r270 bottom (schematic designator C8)
C9_M1 "10uF 10V" C0402 59.991,63.31 r0 bottom (schematic designator C9)
C9_M2 "10uF 10V" C0402 60.043,27.028 r0 bottom (schematic designator C9)
C10_M1 "0.1uF 50V" C0402 50.571,66.485 r0 bottom (schematic designator C10)
C10_M2 "0.1uF 50V" C0402 50.762,30.068 r0 bottom (schematic designator C10)
C11_M1 "0.1uF 50V" C0402 53.552,68.644 r180 bottom (schematic designator C11)
C11_M2 "0.1uF 50V" C0402 53.604,32.362 r180 bottom (schematic designator C11)
C12_M1 "0.1uF 50V" C0402 58.34,70.93 r180 bottom (schematic designator C12)
C12_M2 "0.1uF 50V" C0402 58.392,34.648 r180 bottom (schematic designator C12)
C13 "10uF 25V" C0603 84.644,84.9 r0 top
C14 "10nF 25V" C0402 84.544,82.106 r0 top
C15 "10nF 25V" C0402 82.479,47.689 r90 top
C16 "22uF 16V" C0603 75.494,43.837 r90 top
C17 "22uF 16V" C0603 75.048,47.712 r0 top
C18 "10nF 25V" C0402 74.224,43.498 r90 top
C19 "10nF 25V" C0402 81.082,47.689 r90 top
C20 "10uF 25V" C0603 78.477,49.49 r0 top
C21 "NA" C0402 81.082,45.068 r270 top
C22 "10nF 25V" C0402 82.495,38.915 r90 top
C23 "22uF 16V" C0603 74.24,34.724 r90 top
C24 "10nF 25V" C0402 81.098,38.915 r90 top
C25 "10nF 25V" C0402 77.161,34.555 r90 top
C26 "10uF 25V" C0603 75.064,38.938 r0 top
C27 "22uF 16V" C0603 78.493,40.716 r0 top
C28 "NA" C0402 81.098,36.294 r270 top
C29_LS1 "0.1uF 50V" C0402 75.661,17.943 r180 top (schematic designator C29)
C29_LS2 "0.1uF 50V" C0402 71.574,19.467 r180 top (schematic designator C29)
C29_LS3 "0.1uF 50V" C0402 86.344,15.911 r180 bottom (schematic designator C29)
C29_LS4 "0.1uF 50V" C0402 79.702,14.73 r90 bottom (schematic designator C29)
C30_LS1 "0.1uF 50V" C0402 75.661,18.959 r180 top (schematic designator C30)
C30_LS2 "0.1uF 50V" C0402 71.574,18.324 r180 top (schematic designator C30)
C30_LS3 "0.1uF 50V" C0402 84.782,15.111 r90 bottom (schematic designator C30)
C30_LS4 "0.1uF 50V" C0402 80.629,16.292 r180 bottom (schematic designator C30)
C31_A1 "1uF 25V" C0402 10.01,78.624 r0 top (schematic designator C31)
C31_A2 "1uF 25V" C0402 10.01,69.607 r0 top (schematic designator C31)
C31_A3 "1uF 25V" C0402 10.899,46.751 r0 top (schematic designator C31)
C31_A4 "1uF 25V" C0402 10.074,33.539 r0 top (schematic designator C31)
C32_A1 "1uF 25V" C0402 15.24,79.385 r0 top (schematic designator C32)
C32_A2 "1uF 25V" C0402 15.24,70.368 r0 top (schematic designator C32)
C32_A3 "1uF 25V" C0402 16.129,47.513 r0 top (schematic designator C32)
C32_A4 "1uF 25V" C0402 15.304,34.301 r0 top (schematic designator C32)
C33_A1 "16pF 50V" C0402 29.257,78.623 r270 top (schematic designator C33)
C33_A2 "16pF 50V" C0402 29.257,69.606 r270 top (schematic designator C33)
C33_A3 "16pF 50V" C0402 30.146,46.751 r270 top (schematic designator C33)
C33_A4 "16pF 50V" C0402 29.321,33.539 r270 top (schematic designator C33)
C34_A1 "11pF 50V" C0402 27.098,78.519 r270 top (schematic designator C34)
C34_A2 "11pF 50V" C0402 27.098,69.502 r270 top (schematic designator C34)
C34_A3 "11pF 50V" C0402 27.987,46.646 r270 top (schematic designator C34)
C34_A4 "11pF 50V" C0402 27.162,33.435 r270 top (schematic designator C34)
C35_A1 "10pF 50V" C0402 25.066,78.519 r270 top (schematic designator C35)
C35_A2 "10pF 50V" C0402 25.066,69.502 r270 top (schematic designator C35)
C35_A3 "10pF 50V" C0402 25.955,46.646 r270 top (schematic designator C35)
C35_A4 "10pF 50V" C0402 25.13,33.435 r270 top (schematic designator C35)
C36_A1 "13pF 50V" C0402 23.161,78.496 r270 top (schematic designator C36)
C36_A2 "13pF 50V" C0402 23.161,69.479 r270 top (schematic designator C36)
C36_A3 "13pF 50V" C0402 24.05,46.624 r270 top (schematic designator C36)
C36_A4 "13pF 50V" C0402 23.225,33.412 r270 top (schematic designator C36)
C37_A1 "1uF 25V" C0402 12.611,79.756 r180 bottom (schematic designator C37)
C37_A2 "1uF 25V" C0402 12.611,70.739 r180 bottom (schematic designator C37)
C37_A3 "1uF 25V" C0402 13.5,47.883 r180 bottom (schematic designator C37)
C37_A4 "1uF 25V" C0402 12.675,34.671 r180 bottom (schematic designator C37)
C38_A1 "0.1uF 50V" C0402 12.596,80.772 r180 bottom (schematic designator C38)
C38_A2 "0.1uF 50V" C0402 12.596,71.755 r180 bottom (schematic designator C38)
C38_A3 "0.1uF 50V" C0402 13.485,48.899 r180 bottom (schematic designator C38)
C38_A4 "0.1uF 50V" C0402 12.66,35.687 r180 bottom (schematic designator C38)
C39_A1 "0.1uF 50V" C0402 39.751,76.932 r270 bottom (schematic designator C39)
C39_A2 "0.1uF 50V" C0402 39.751,67.915 r270 bottom (schematic designator C39)
C39_A3 "0.1uF 50V" C0402 40.64,45.059 r270 bottom (schematic designator C39)
C39_A4 "0.1uF 50V" C0402 39.815,31.847 r270 bottom (schematic designator C39)
C40_A1 "1uF 25V" C0402 39.243,75.408 r0 bottom (schematic designator C40)
C40_A2 "1uF 25V" C0402 39.243,66.391 r0 bottom (schematic designator C40)
C40_A3 "1uF 25V" C0402 40.132,43.535 r0 bottom (schematic designator C40)
C40_A4 "1uF 25V" C0402 39.307,30.323 r0 bottom (schematic designator C40)
C41_A1 "0.1uF 50V" C0402 48.561,78.146 r90 bottom (schematic designator C41)
C41_A2 "0.1uF 50V" C0402 48.561,69.129 r90 bottom (schematic designator C41)
C41_A3 "0.1uF 50V" C0402 49.45,46.274 r90 bottom (schematic designator C41)
C41_A4 "0.1uF 50V" C0402 48.625,33.062 r90 bottom (schematic designator C41)
C42_A1 "0.1uF 50V" C0402 47.037,80.201 r0 bottom (schematic designator C42)
C42_A2 "0.1uF 50V" C0402 47.037,71.184 r0 bottom (schematic designator C42)
C42_A3 "0.1uF 50V" C0402 47.926,48.328 r0 bottom (schematic designator C42)
C42_A4 "0.1uF 50V" C0402 47.101,35.117 r0 bottom (schematic designator C42)
C43_A1 "10uF 10V" C0402 47.037,79.185 r0 bottom (schematic designator C43)
C43_A2 "10uF 10V" C0402 47.037,70.168 r0 bottom (schematic designator C43)
C43_A3 "10uF 10V" C0402 47.926,47.312 r0 bottom (schematic designator C43)
C43_A4 "10uF 10V" C0402 47.101,34.101 r0 bottom (schematic designator C43)
C44_B1 "1uF 25V" c0402 174.244,-10.691 r90 top (schematic designator C44)
C44_B2 "1uF 25V" c0402 176.022,9.602 r90 top (schematic designator C44)
C44_B3 "1uF 25V" C0402 12.297,-5.984 r0 top (schematic designator C44)
C44_B4 "1uF 25V" C0402 10.074,15.505 r0 top (schematic designator C44)
C45_B1 "1uF 25V" c0402 184.15,-10.691 r90 top (schematic designator C45)
C45_B2 "1uF 25V" c0402 186.436,9.602 r90 top (schematic designator C45)
C45_B3 "1uF 25V" C0402 17.526,-5.222 r0 top (schematic designator C45)
C45_B4 "1uF 25V" C0402 15.304,16.267 r0 top (schematic designator C45)
C46_B1 "16pF 50V" c0402 154.432,-10.691 r90 top (schematic designator C46)
C46_B2 "16pF 50V" c0402 155.194,9.602 r90 top (schematic designator C46)
C46_B3 "16pF 50V" C0402 31.543,-5.984 r270 top (schematic designator C46)
C46_B4 "16pF 50V" C0402 29.321,15.505 r270 top (schematic designator C46)
C47_B1 "11pF 50V" c0402 164.338,-10.691 r90 top (schematic designator C47)
C47_B2 "11pF 50V" c0402 165.608,9.602 r90 top (schematic designator C47)
C47_B3 "11pF 50V" C0402 29.384,-6.088 r270 top (schematic designator C47)
C47_B4 "11pF 50V" C0402 27.162,15.401 r270 top (schematic designator C47)
C48_B1 "10pF 50V" c0402 105.156,-10.31 r90 top (schematic designator C48)
C48_B2 "10pF 50V" c0402 103.378,10.364 r90 top (schematic designator C48)
C48_B3 "10pF 50V" C0402 27.352,-6.088 r270 top (schematic designator C48)
C48_B4 "10pF 50V" C0402 25.13,15.401 r270 top (schematic designator C48)
C49_B1 "13pF 50V" c0402 115.062,-10.31 r90 top (schematic designator C49)
C49_B2 "13pF 50V" c0402 113.792,10.364 r90 top (schematic designator C49)
C49_B3 "13pF 50V" C0402 25.447,-6.111 r270 top (schematic designator C49)
C49_B4 "13pF 50V" C0402 23.225,15.378 r270 top (schematic designator C49)
C50_B1 "1uF 25V" c0402 105.156,-10.691 r90 top (schematic designator C50)
C50_B2 "1uF 25V" c0402 103.378,9.602 r90 top (schematic designator C50)
C50_B3 "1uF 25V" C0402 14.897,-4.852 r180 bottom (schematic designator C50)
C50_B4 "1uF 25V" C0402 12.675,16.637 r180 bottom (schematic designator C50)
C51_B1 "0.1uF 50V" c0402 115.062,-10.691 r90 top (schematic designator C51)
C51_B2 "0.1uF 50V" c0402 113.792,9.602 r90 top (schematic designator C51)
C51_B3 "0.1uF 50V" C0402 14.882,-3.836 r180 bottom (schematic designator C51)
C51_B4 "0.1uF 50V" C0402 12.66,17.653 r180 bottom (schematic designator C51)
C52_B1 "0.1uF 50V" c0402 105.156,-10.691 r90 top (schematic designator C52)
C52_B2 "0.1uF 50V" c0402 103.378,9.602 r90 top (schematic designator C52)
C52_B3 "0.1uF 50V" C0402 42.037,-7.676 r270 bottom (schematic designator C52)
C52_B4 "0.1uF 50V" C0402 39.815,13.813 r270 bottom (schematic designator C52)
C53_B1 "1uF 25V" c0402 115.062,-10.691 r90 top (schematic designator C53)
C53_B2 "1uF 25V" c0402 113.792,9.602 r90 top (schematic designator C53)
C53_B3 "1uF 25V" C0402 41.529,-9.2 r0 bottom (schematic designator C53)
C53_B4 "1uF 25V" C0402 39.307,12.289 r0 bottom (schematic designator C53)
C54_B1 "0.1uF 50V" c0402 124.714,-10.691 r90 top (schematic designator C54)
C54_B2 "0.1uF 50V" c0402 123.952,9.602 r90 top (schematic designator C54)
C54_B3 "0.1uF 50V" C0402 50.848,-6.461 r90 bottom (schematic designator C54)
C54_B4 "0.1uF 50V" C0402 48.625,15.028 r90 bottom (schematic designator C54)
C55_B1 "0.1uF 50V" c0402 134.62,-10.691 r90 top (schematic designator C55)
C55_B2 "0.1uF 50V" c0402 141.224,13.297 r90 top (schematic designator C55)
C55_B3 "0.1uF 50V" C0402 49.324,-4.406 r0 bottom (schematic designator C55)
C55_B4 "0.1uF 50V" C0402 47.101,17.083 r0 bottom (schematic designator C55)
C56_B1 "10uF 10V" c0402 144.526,-10.691 r90 top (schematic designator C56)
C56_B2 "10uF 10V" c0402 144.78,9.602 r90 top (schematic designator C56)
C56_B3 "10uF 10V" C0402 49.324,-5.422 r0 bottom (schematic designator C56)
C56_B4 "10uF 10V" C0402 47.101,16.067 r0 bottom (schematic designator C56)
F1 "PTC 24V / 1.5A" 1812_F 62.611,14.921 r90 top
F2 "PTC 24V / 1.5A" 1812_F 66.294,14.921 r90 top
F3 "PTC 24V / 1.5A" 1812_F 58.928,14.921 r270 top
FB1_M1 "BLM18EG221SN1D" FB0603 57.389,63.437 r180 bottom (schematic designator FB1)
FB1_M2 "BLM18EG221SN1D" FB0603 57.441,27.155 r180 bottom (schematic designator FB1)
FB2 "BLM18EG221SN1D" FB0603 81.782,49.49 r180 top
FB3 "BLM18EG221SN1D" FB0603 75.048,45.553 r180 top
FB4 "BLM18EG221SN1D" FB0603 81.798,40.716 r180 top
FB5 "BLM18EG221SN1D" FB0603 75.064,36.779 r180 top
FID1 "Fiducial" FIDUCIAL 72.644,85.408 r90 top
FID2 "Fiducial" FIDUCIAL 94.107,13.145 r90 top
FID3 "Fiducial" FIDUCIAL 11.049,7.43 r90 top
FID4 "Fiducial" FIDUCIAL 72.771,85.408 r90 bottom
FID5 "Fiducial" FIDUCIAL 94.234,13.145 r90 bottom
FID6 "Fiducial" FIDUCIAL 11.303,7.43 r90 bottom
H1 "Hole 3mm" "HOLE 3MM" 97.762,78.509 r0 top
H2 "Hole 3mm" "HOLE 3MM" 4.762,84.509 r0 top
H3 "Hole 3mm" "HOLE 3MM" 97.762,15.009 r0 top
H4 "Hole 3mm" "HOLE 3MM" 4.762,8.009 r0 top
J1 "1053141204" CON_1053141204 88.559,85.027 r90 top
J2 "5767096-1" MICTOR-38_PIN 88.326,68.776 r90 top
J3 "90131-0770" HEADER_10X2 67.421,76.518 r270 top
J4 "90131-0770" HEADER_10X2 82.153,76.391 r270 top
J5 "90131-0770" HEADER_10X2 74.914,76.518 r270 top
J6 "10018784-10201TLF" PCIE_8LANE_EDGE 71.379,6.521 r0 top locked
J7_A1 "SMA-J-P-H-RA-TH1" CONN_SMA-J-P-H-RA-TH1_SAI 4.572,78.613 r90 top (schematic designator J7)
J7_A2 "SMA-J-P-H-RA-TH1" CONN_SMA-J-P-H-RA-TH1_SAI 4.572,69.596 r90 top (schematic designator J7)
J7_A3 "SMA-J-P-H-RA-TH1" CONN_SMA-J-P-H-RA-TH1_SAI 5.461,46.74 r90 top (schematic designator J7)
J7_A4 "SMA-J-P-H-RA-TH1" CONN_SMA-J-P-H-RA-TH1_SAI 4.636,33.528 r90 top (schematic designator J7)
J8_A1 "MMCX-J-P-H-ST-TH1" SAMTEC_MMCX-J-P-H-ST-TH1 37.846,81.407 r270 top (schematic designator J8)
J8_A2 "MMCX-J-P-H-ST-TH1" SAMTEC_MMCX-J-P-H-ST-TH1 37.846,72.39 r270 top (schematic designator J8)
J8_A3 "MMCX-J-P-H-ST-TH1" SAMTEC_MMCX-J-P-H-ST-TH1 38.735,49.534 r270 top (schematic designator J8)
J8_A4 "MMCX-J-P-H-ST-TH1" SAMTEC_MMCX-J-P-H-ST-TH1 37.91,36.322 r270 top (schematic designator J8)
J9_B1 "SMA-J-P-H-RA-TH1" CONN_SMA-J-P-H-RA-TH1_SAI 168.021,-5.992 r90 top (schematic designator J9)
J9_B2 "SMA-J-P-H-RA-TH1" CONN_SMA-J-P-H-RA-TH1_SAI 166.37,21.794 r90 top (schematic designator J9)
J9_B3 "SMA-J-P-H-RA-TH1" CONN_SMA-J-P-H-RA-TH1_SAI 6.858,-5.995 r90 top (schematic designator J9)
J9_B4 "SMA-J-P-H-RA-TH1" CONN_SMA-J-P-H-RA-TH1_SAI 4.636,15.494 r90 top (schematic designator J9)
J10_B1 "MMCX-J-P-H-ST-TH1" SAMTEC_MMCX-J-P-H-ST-TH1 137.033,-3.071 r90 top (schematic designator J10)
J10_B2 "MMCX-J-P-H-ST-TH1" SAMTEC_MMCX-J-P-H-ST-TH1 135.509,24.715 r90 top (schematic designator J10)
J10_B3 "MMCX-J-P-H-ST-TH1" SAMTEC_MMCX-J-P-H-ST-TH1 40.132,-3.201 r270 top (schematic designator J10)
J10_B4 "MMCX-J-P-H-ST-TH1" SAMTEC_MMCX-J-P-H-ST-TH1 37.91,18.288 r270 top (schematic designator J10)
L1_A1 "Inductor" 0402-A 28.241,79.893 r180 top value=56nH (schematic designator L1)
L1_A2 "Inductor" 0402-A 28.241,70.876 r180 top value=56nH (schematic designator L1)
L1_A3 "Inductor" 0402-A 29.13,48.021 r180 top value=56nH (schematic designator L1)
L1_A4 "Inductor" 0402-A 28.305,34.809 r180 top value=56nH (schematic designator L1)
L2_A1 "Inductor" 0402-A 30.392,79.894 r180 top value=43nH (schematic designator L2)
L2_A2 "Inductor" 0402-A 30.392,70.877 r180 top value=43nH (schematic designator L2)
L2_A3 "Inductor" 0402-A 31.281,48.021 r180 top value=43nH (schematic designator L2)
L2_A4 "Inductor" 0402-A 30.456,34.809 r180 top value=43nH (schematic designator L2)
L3_A1 "Inductor" 0402-A 26.082,79.893 r180 top value=43nH (schematic designator L3)
L3_A2 "Inductor" 0402-A 26.082,70.876 r180 top value=43nH (schematic designator L3)
L3_A3 "Inductor" 0402-A 26.971,48.021 r180 top value=43nH (schematic designator L3)
L3_A4 "Inductor" 0402-A 26.146,34.809 r180 top value=43nH (schematic designator L3)
L4_A1 "Inductor" 0402-A 24.05,79.893 r180 top value=47nH (schematic designator L4)
L4_A2 "Inductor" 0402-A 24.05,70.876 r180 top value=47nH (schematic designator L4)
L4_A3 "Inductor" 0402-A 24.939,48.021 r180 top value=47nH (schematic designator L4)
L4_A4 "Inductor" 0402-A 24.114,34.809 r180 top value=47nH (schematic designator L4)
L5_A1 "Inductor" 0402-A 21.891,79.893 r180 top value=33nH (schematic designator L5)
L5_A2 "Inductor" 0402-A 21.891,70.876 r180 top value=33nH (schematic designator L5)
L5_A3 "Inductor" 0402-A 22.78,48.021 r180 top value=33nH (schematic designator L5)
L5_A4 "Inductor" 0402-A 21.955,34.809 r180 top value=33nH (schematic designator L5)
L6_A1 "Inductor" 0402-A 27.098,76.345 r270 top value=24nH (schematic designator L6)
L6_A2 "Inductor" 0402-A 27.098,67.328 r270 top value=24nH (schematic designator L6)
L6_A3 "Inductor" 0402-A 27.987,44.473 r270 top value=24nH (schematic designator L6)
L6_A4 "Inductor" 0402-A 27.162,31.261 r270 top value=24nH (schematic designator L6)
L7_A1 "Inductor" 0402-A 25.066,76.345 r270 top value=33nH (schematic designator L7)
L7_A2 "Inductor" 0402-A 25.066,67.328 r270 top value=33nH (schematic designator L7)
L7_A3 "Inductor" 0402-A 25.955,44.473 r270 top value=33nH (schematic designator L7)
L7_A4 "Inductor" 0402-A 25.13,31.261 r270 top value=33nH (schematic designator L7)
L8_A1 "Inductor" 0402-A 23.161,76.21 r270 top value=15nH (schematic designator L8)
L8_A2 "Inductor" 0402-A 23.161,67.193 r270 top value=15nH (schematic designator L8)
L8_A3 "Inductor" 0402-A 24.05,44.338 r270 top value=15nH (schematic designator L8)
L8_A4 "Inductor" 0402-A 23.225,31.126 r270 top value=15nH (schematic designator L8)
L9_A1 "Inductor" 0402-A 29.257,76.345 r270 top value=3.9nH (schematic designator L9)
L9_A2 "Inductor" 0402-A 29.257,67.328 r270 top value=3.9nH (schematic designator L9)
L9_A3 "Inductor" 0402-A 30.146,44.473 r270 top value=3.9nH (schematic designator L9)
L9_A4 "Inductor" 0402-A 29.321,31.261 r270 top value=3.9nH (schematic designator L9)
L10_B1 "Inductor" 0402-A 124.587,-1.928 r90 top value=56nH (schematic designator L10)
L10_B2 "Inductor" 0402-A 122.936,25.858 r90 top value=56nH (schematic designator L10)
L10_B3 "Inductor" 0402-A 30.527,-4.714 r180 top value=56nH (schematic designator L10)
L10_B4 "Inductor" 0402-A 28.305,16.775 r180 top value=56nH (schematic designator L10)
L11_B1 "Inductor" 0402-A 120.65,-1.928 r90 top value=43nH (schematic designator L11)
L11_B2 "Inductor" 0402-A 118.999,25.858 r90 top value=43nH (schematic designator L11)
L11_B3 "Inductor" 0402-A 32.678,-4.714 r180 top value=43nH (schematic designator L11)
L11_B4 "Inductor" 0402-A 30.456,16.775 r180 top value=43nH (schematic designator L11)
L12_B1 "Inductor" 0402-A 122.555,-1.928 r90 top value=43nH (schematic designator L12)
L12_B2 "Inductor" 0402-A 120.904,25.858 r90 top value=43nH (schematic designator L12)
L12_B3 "Inductor" 0402-A 28.368,-4.714 r180 top value=43nH (schematic designator L12)
L12_B4 "Inductor" 0402-A 26.146,16.775 r180 top value=43nH (schematic designator L12)
L13_B1 "Inductor" 0402-A 112.903,-1.928 r90 top value=47nH (schematic designator L13)
L13_B2 "Inductor" 0402-A 111.125,25.858 r90 top value=47nH (schematic designator L13)
L13_B3 "Inductor" 0402-A 26.336,-4.714 r180 top value=47nH (schematic designator L13)
L13_B4 "Inductor" 0402-A 24.114,16.775 r180 top value=47nH (schematic designator L13)
L14_B1 "Inductor" 0402-A 114.808,-1.928 r90 top value=33nH (schematic designator L14)
L14_B2 "Inductor" 0402-A 113.03,25.858 r90 top value=33nH (schematic designator L14)
L14_B3 "Inductor" 0402-A 24.177,-4.714 r180 top value=33nH (schematic designator L14)
L14_B4 "Inductor" 0402-A 21.955,16.775 r180 top value=33nH (schematic designator L14)
L15_B1 "Inductor" 0402-A 105.029,-1.928 r90 top value=3.9nH (schematic designator L15)
L15_B2 "Inductor" 0402-A 103.251,25.858 r90 top value=3.9nH (schematic designator L15)
L15_B3 "Inductor" 0402-A 31.543,-8.262 r270 top value=3.9nH (schematic designator L15)
L15_B4 "Inductor" 0402-A 29.321,13.227 r270 top value=3.9nH (schematic designator L15)
L16_B1 "Inductor" 0402-A 106.934,-1.928 r90 top value=24nH (schematic designator L16)
L16_B2 "Inductor" 0402-A 105.156,25.858 r90 top value=24nH (schematic designator L16)
L16_B3 "Inductor" 0402-A 29.384,-8.262 r270 top value=24nH (schematic designator L16)
L16_B4 "Inductor" 0402-A 27.162,13.227 r270 top value=24nH (schematic designator L16)
L17_B1 "Inductor" 0402-A 108.966,-1.928 r90 top value=33nH (schematic designator L17)
L17_B2 "Inductor" 0402-A 107.188,25.858 r90 top value=33nH (schematic designator L17)
L17_B3 "Inductor" 0402-A 27.352,-8.262 r270 top value=33nH (schematic designator L17)
L17_B4 "Inductor" 0402-A 25.13,13.227 r270 top value=33nH (schematic designator L17)
L18_B1 "Inductor" 0402-A 110.871,-1.928 r90 top value=15nH (schematic designator L18)
L18_B2 "Inductor" 0402-A 109.093,25.858 r90 top value=15nH (schematic designator L18)
L18_B3 "Inductor" 0402-A 25.447,-8.397 r270 top value=15nH (schematic designator L18)
L18_B4 "Inductor" 0402-A 23.225,13.092 r270 top value=15nH (schematic designator L18)
LD1 "APT1608SGC" LED_0603_GREEN 70.088,47.638 r90 top
LD2 "APT1608SGC" LED_0603_GREEN 70.104,38.864 r90 top
Lp1 "NR6028T100M" IND6X6_H3 90.034,42.228 r180 top
R1_M1 "6.8K" R0402 59.991,64.707 r0 bottom (schematic designator R1)
R1_M2 "6.8K" R0402 60.043,28.425 r0 bottom (schematic designator R1)
R2_M1 "0R" R0402 60.118,69.914 r180 bottom (schematic designator R2)
R2_M2 "0R" R0402 60.17,33.632 r180 bottom (schematic designator R2)
R3_M1 "10K" R0402 87.884,19.073 r270 top (schematic designator R3)
R3_M2 "10K" R0402 82.169,19.177 r270 top (schematic designator R3)
R4_M1 "10K" R0402 86.868,19.073 r270 top (schematic designator R4)
R4_M2 "10K" R0402 81.153,19.177 r270 top (schematic designator R4)
R5_M1 "10K" R0402 85.852,19.073 r270 top (schematic designator R5)
R5_M2 "10K" R0402 80.137,19.177 r270 top (schematic designator R5)
R6_M1 "10K" R0402 84.836,19.073 r270 top (schematic designator R6)
R6_M2 "10K" R0402 79.121,19.177 r270 top (schematic designator R6)
R7_M1 "NA" R0402 53.044,63.31 r180 bottom (schematic designator R7)
R7_M2 "NA" R0402 53.096,27.028 r180 bottom (schematic designator R7)
R8_M1 "0R" R0402 60.626,66.396 r270 bottom (schematic designator R8)
R8_M2 "0R" R0402 60.678,30.115 r270 bottom (schematic designator R8)
R9_M1 "0R" R0402 54.53,63.841 r270 bottom (schematic designator R9)
R9_M2 "0R" R0402 54.582,27.559 r270 bottom (schematic designator R9)
R10_M1 "NA" R0402 60.08,67.882 r0 bottom (schematic designator R10)
R10_M2 "NA" R0402 60.132,31.6 r0 bottom (schematic designator R10)
R11_M1 "10K" R0402 56.054,70.168 r90 bottom (schematic designator R11)
R11_M2 "10K" R0402 56.106,33.886 r90 bottom (schematic designator R11)
R12_M1 "10K" R0402 55.038,70.168 r90 bottom (schematic designator R12)
R12_M2 "10K" R0402 55.09,33.886 r90 bottom (schematic designator R12)
R13_M1 "10K" R0402 54.022,70.168 r90 bottom (schematic designator R13)
R13_M2 "10K" R0402 54.074,33.886 r90 bottom (schematic designator R13)
R14_M1 "10K" R0402 53.006,70.168 r90 bottom (schematic designator R14)
R14_M2 "10K" R0402 53.058,33.886 r90 bottom (schematic designator R14)
R15_M1 "0R" R0805 52.371,55.563 r180 bottom (schematic designator R15)
R15_M2 "0R" R0805 52.435,18.574 r180 bottom (schematic designator R15)
R16_M1 "0R" R0805 52.371,57.595 r180 bottom (schematic designator R16)
R16_M2 "0R" R0805 52.435,20.606 r180 bottom (schematic designator R16)
R17_M1 "0R" R0805 52.625,72.708 r180 bottom (schematic designator R17)
R17_M2 "0R" R0805 52.689,35.719 r180 bottom (schematic designator R17)
R18_M1 "0R" R0805 52.625,82.487 r180 bottom (schematic designator R18)
R18_M2 "0R" R0805 52.689,45.498 r180 bottom (schematic designator R18)
R19_M1 "0R" R0805 52.371,52.007 r180 bottom (schematic designator R19)
R19_M2 "0R" R0805 52.435,15.018 r180 bottom (schematic designator R19)
R20_M1 "0R" R0805 52.371,59.373 r180 bottom (schematic designator R20)
R20_M2 "0R" R0805 52.435,22.384 r180 bottom (schematic designator R20)
R21_M1 "0R" R0805 52.625,76.264 r180 bottom (schematic designator R21)
R21_M2 "0R" R0805 52.689,39.275 r180 bottom (schematic designator R21)
R22_M1 "0R" R0805 52.625,80.709 r180 bottom (schematic designator R22)
R22_M2 "0R" R0805 52.689,43.72 r180 bottom (schematic designator R22)
R23_M1 "0R" R0805 52.371,53.785 r180 bottom (schematic designator R23)
R23_M2 "0R" R0805 52.435,16.796 r180 bottom (schematic designator R23)
R24_M1 "0R" R0805 52.371,61.024 r180 bottom (schematic designator R24)
R24_M2 "0R" R0805 52.435,24.035 r180 bottom (schematic designator R24)
R25_M1 "0R" R0805 52.625,74.486 r180 bottom (schematic designator R25)
R25_M2 "0R" R0805 52.689,37.497 r180 bottom (schematic designator R25)
R26_M1 "0R" R0805 52.625,78.931 r180 bottom (schematic designator R26)
R26_M2 "0R" R0805 52.689,41.942 r180 bottom (schematic designator R26)
R27 "124K" R0402 78.415,43.544 r270 top
R28 "1K" R0402 70.033,45.337 r270 top
R29 "39.2K" R0402 79.431,43.498 r90 top
R30 "124K" R0402 78.431,34.77 r270 top
R31 "1K" R0402 70.049,36.563 r270 top
R32 "100K" R0402 79.447,34.724 r90 top
R33 "0R" R0402 58.547,49.238 r90 top
R34_LS1 "100K" R0402 73.86,16.673 r270 top (schematic designator R34)
R34_LS2 "100K" R0402 69.542,16.546 r90 top (schematic designator R34)
R34_LS3 "100K" R0402 83.639,16.673 r90 top (schematic designator R34)
R34_LS4 "100K" R0402 78.432,16.546 r90 top (schematic designator R34)
R35_LS1 "NA" R0402 73.86,14.514 r90 top (schematic designator R35)
R35_LS2 "NA" R0402 69.542,14.349 r90 top (schematic designator R35)
R35_LS3 "NA" R0402 83.639,14.491 r90 top (schematic designator R35)
R35_LS4 "NA" R0402 78.432,14.387 r90 top (schematic designator R35)
R36_A1 "34.8R" R0402 17.167,79.893 r180 top (schematic designator R36)
R36_A2 "34.8R" R0402 17.167,70.876 r180 top (schematic designator R36)
R36_A3 "34.8R" R0402 18.056,48.021 r180 top (schematic designator R36)
R36_A4 "34.8R" R0402 17.231,34.809 r180 top (schematic designator R36)
R37_A1 "34.8R" R0402 20.003,79.894 r180 top (schematic designator R37)
R37_A2 "34.8R" R0402 20.003,70.877 r180 top (schematic designator R37)
R37_A3 "34.8R" R0402 20.892,48.021 r180 top (schematic designator R37)
R37_A4 "34.8R" R0402 20.067,34.809 r180 top (schematic designator R37)
R38_A1 "18.2R" R0402 18.542,79.424 r270 top (schematic designator R38)
R38_A2 "18.2R" R0402 18.542,70.407 r270 top (schematic designator R38)
R38_A3 "18.2R" R0402 19.431,47.551 r270 top (schematic designator R38)
R38_A4 "18.2R" R0402 18.606,34.339 r270 top (schematic designator R38)
R39_A1 "49.9R" R0402 48.561,78.131 r90 top (schematic designator R39)
R39_A2 "49.9R" R0402 48.561,69.114 r90 top (schematic designator R39)
R39_A3 "49.9R" R0402 49.45,46.258 r90 top (schematic designator R39)
R39_A4 "49.9R" R0402 48.625,33.046 r90 top (schematic designator R39)
R40_A1 "49.9R" R0402 48.561,82.195 r90 top (schematic designator R40)
R40_A2 "49.9R" R0402 48.561,73.178 r90 top (schematic designator R40)
R40_A3 "49.9R" R0402 49.45,50.322 r90 top (schematic designator R40)
R40_A4 "49.9R" R0402 48.625,37.11 r90 top (schematic designator R40)
R41_A1 "NA" R0402 32.601,80.391 r0 top (schematic designator R41)
R41_A2 "NA" R0402 32.601,71.374 r0 top (schematic designator R41)
R41_A3 "NA" R0402 33.49,48.518 r0 top (schematic designator R41)
R41_A4 "NA" R0402 32.665,35.306 r0 top (schematic designator R41)
R42_A1 "0R" R0402 32.662,79.375 r180 top (schematic designator R42)
R42_A2 "0R" R0402 32.662,70.358 r180 top (schematic designator R42)
R42_A3 "0R" R0402 33.551,47.502 r180 top (schematic designator R42)
R42_A4 "0R" R0402 32.726,34.29 r180 top (schematic designator R42)
R43_B1 "34.8R" r0402 152.019,-2.055 r90 top (schematic designator R43)
R43_B2 "34.8R" r0402 150.495,25.731 r90 top (schematic designator R43)
R43_B3 "34.8R" R0402 19.454,-4.714 r180 top (schematic designator R43)
R43_B4 "34.8R" R0402 17.231,16.775 r180 top (schematic designator R43)
R44_B1 "34.8R" r0402 154.305,-2.055 r90 top (schematic designator R44)
R44_B2 "34.8R" r0402 152.781,25.731 r90 top (schematic designator R44)
R44_B3 "34.8R" R0402 22.289,-4.714 r180 top (schematic designator R44)
R44_B4 "34.8R" R0402 20.067,16.775 r180 top (schematic designator R44)
R45_B1 "18.2R" r0402 149.733,-2.055 r90 top (schematic designator R45)
R45_B2 "18.2R" r0402 148.209,25.731 r90 top (schematic designator R45)
R45_B3 "18.2R" R0402 20.828,-5.184 r270 top (schematic designator R45)
R45_B4 "18.2R" R0402 18.606,16.305 r270 top (schematic designator R45)
R46_B1 "49.9R" r0402 134.874,-10.31 r90 top (schematic designator R46)
R46_B2 "49.9R" r0402 146.304,25.565 r270 top (schematic designator R46)
R46_B3 "49.9R" R0402 50.8,-2.439 r270 top (schematic designator R46)
R46_B4 "49.9R" R0402 48.578,19.073 r270 top (schematic designator R46)
R47_B1 "49.9R" r0402 124.968,-10.31 r90 top (schematic designator R47)
R47_B2 "49.9R" r0402 146.685,20.193 r90 top (schematic designator R47)
R47_B3 "49.9R" R0402 50.848,-6.477 r270 top (schematic designator R47)
R47_B4 "49.9R" R0402 48.705,14.986 r270 top (schematic designator R47)
R48_B1 "NA" r0402 127.508,-1.547 r0 top (schematic designator R48)
R48_B2 "NA" r0402 125.857,26.239 r0 top (schematic designator R48)
R48_B3 "NA" R0402 34.887,-4.217 r0 top (schematic designator R48)
R48_B4 "NA" R0402 32.665,17.272 r0 top (schematic designator R48)
R49_B1 "0R" r0402 117.729,-1.547 r0 top (schematic designator R49)
R49_B2 "0R" r0402 116.078,26.239 r0 top (schematic designator R49)
R49_B3 "0R" R0402 34.948,-5.233 r180 top (schematic designator R49)
R49_B4 "0R" R0402 32.726,16.256 r180 top (schematic designator R49)
SH1_M1 "RF_SHIELD" SMS201F 56.868,30.838 r0 top (schematic designator SH1)
SH1_M2 "RF_SHIELD" SMS201F 56.816,67.12 r0 top (schematic designator SH1)
T1_A1 "ADTT1-1+" CD542_MNC 44.191,80.168 r180 top (schematic designator T1)
T1_A2 "ADTT1-1+" CD542_MNC 44.191,71.151 r180 top (schematic designator T1)
T1_A3 "ADTT1-1+" CD542_MNC 45.08,48.295 r180 top (schematic designator T1)
T1_A4 "ADTT1-1+" CD542_MNC 44.255,35.084 r180 top (schematic designator T1)
T2_B1 "ADTT1-1+" CD542_MNC 144.145,-5.23 r0 top (schematic designator T2)
T2_B2 "ADTT1-1+" CD542_MNC 141.958,23.876 r180 top (schematic designator T2)
T2_B3 "ADTT1-1+" CD542_MNC 46.478,-4.439 r180 top (schematic designator T2)
T2_B4 "ADTT1-1+" CD542_MNC 44.255,17.05 r180 top (schematic designator T2)
TP1 "+12V" TP_2X1.8 86.995,36.386 r270 top
TP2 "+3.3V" TP_2X1.8 72.319,45.553 r90 top
TP3 "+1.8V" TP_2X1.8 72.335,36.779 r90 top
TP4 "SyncIn" TP_2X1.8 62.357,58.103 r90 top
TP5 "SyncOut" TP_2X1.8 62.484,21.4 r270 top
TP6 "GND" TP_2X1.8 98.044,73.47 r270 top
TP7 "GND" TP_2X1.8 97.917,18.987 r0 top
U1_M1 "AD9959BCPZ" CP_56_1_ADI 56.816,67.12 r90 top (schematic designator U1)
U1_M2 "AD9959BCPZ" CP_56_1_ADI 56.868,30.838 r90 top (schematic designator U1)
U2 "MUN12AD03-SEC" SO8_MUN12AD_DEA 78.613,46.546 r270 top
U3 "MUN12AD03-SEC" SO8_MUN12AD_DEA 78.629,37.772 r270 top
U4_LS1 "74AVC4T774_GU" NXP_74AVC4T245GU,115 76.181,15.235 r90 top (schematic designator U4)
U4_LS2 "74AVC4T774_GU" NXP_74AVC4T245GU,115 71.701,15.235 r90 top (schematic designator U4)
U4_LS3 "74AVC4T774_GU" NXP_74AVC4T245GU,115 85.798,15.235 r90 top (schematic designator U4)
U4_LS4 "74AVC4T774_GU" NXP_74AVC4T245GU,115 80.718,15.235 r90 top (schematic designator U4)
U5_A1 "BGA2815,115" SOT_2815,115_NXP 12.652,79.259 r0 top (schematic designator U5)
U5_A2 "BGA2815,115" SOT_2815,115_NXP 12.652,70.242 r0 top (schematic designator U5)
U5_A3 "BGA2815,115" SOT_2815,115_NXP 13.541,47.386 r0 top (schematic designator U5)
U5_A4 "BGA2815,115" SOT_2815,115_NXP 12.716,34.174 r0 top (schematic designator U5)
U6_A1 "ADG901BCPZ-500RL7" CP_8_2_ADI 38.227,76.899 r180 top (schematic designator U6)
U6_A2 "ADG901BCPZ-500RL7" CP_8_2_ADI 38.227,67.882 r180 top (schematic designator U6)
U6_A3 "ADG901BCPZ-500RL7" CP_8_2_ADI 39.116,45.026 r180 top (schematic designator U6)
U6_A4 "ADG901BCPZ-500RL7" CP_8_2_ADI 38.291,31.814 r180 top (schematic designator U6)
U7_B1 "BGA2815,115" SOT_2815,115_NXP 174.244,-2.563 r90 top (schematic designator U7)
U7_B2 "BGA2815,115" SOT_2815,115_NXP 172.72,25.223 r90 top (schematic designator U7)
U7_B3 "BGA2815,115" SOT_2815,115_NXP 14.938,-5.349 r0 top (schematic designator U7)
U7_B4 "BGA2815,115" SOT_2815,115_NXP 12.716,16.14 r0 top (schematic designator U7)
U8_B1 "ADG901BCPZ-500RL7" CP_8_2_ADI 131.953,-3.071 r90 top (schematic designator U8)
U8_B2 "ADG901BCPZ-500RL7" CP_8_2_ADI 130.429,24.715 r90 top (schematic designator U8)
U8_B3 "ADG901BCPZ-500RL7" CP_8_2_ADI 40.513,-7.709 r180 top (schematic designator U8)
U8_B4 "ADG901BCPZ-500RL7" CP_8_2_ADI 38.291,13.78 r180 top (schematic designator U8)
Y1_M1 "ECS-250-20-33-CKM-TR3" SMD4_ECX-32_3P2X2P5_ECS 63.51,65.97 r0 bottom (schematic designator Y1)
Y1_M2 "ECS-250-20-33-CKM-TR3" SMD4_ECX-32_3P2X2P5_ECS 64.256,30.886 r0 bottom (schematic designator Y1)

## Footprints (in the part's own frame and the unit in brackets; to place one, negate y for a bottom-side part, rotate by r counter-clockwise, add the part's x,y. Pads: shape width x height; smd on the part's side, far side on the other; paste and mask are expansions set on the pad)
0402-A [mm] "Chip Inductor, Body 1.0x0.5mm, IPC High Density"
  rect 0.6x0.5 smd mask+0.051: 1(-0.5,0) 2(0.5,0)
  silkscreen extent -1.1,-0.15 -1.1,0.15, body extent -0.55,-0.3 0.55,0.3, height 0.55
1812_F [mm] "PTC RESETTABLE 33V 1.10A 1812L"
  rect 1.78x3.15 smd mask+0.051: 1(-2.665,0) 2(2.665,0)
  silkscreen extent -2.4,-1.7 2.4,1.7, body extent -2.36,-1.74 2.37,1.74, height 1.03
C0402 [mil]
  rect 25x25 smd mask+2: 1(-18.5,0) 2(20.9,0)
  silkscreen extent -36,-17 40,17, body extent -20,-12 20,12, height 8
c0402 [mil]
  rect 25x25 smd mask+2: 1(-18.5,0) 2(20.9,0)
  silkscreen extent -36,-17 40,17, body extent -20,-12 20,12, height 8
C0603 [mm]
  rect 0.7x0.9 smd mask+0.051: 1(-0.7,0) 2(0.7,0)
  silkscreen extent -1.2,-0.6 1.2,0.6, body extent -0.8,-0.4 0.8,0.4, height 0.3
CD542_MNC [mm]
  rect 0.96x0.712 smd paste+0 mask+0.051: 1(-3.274,2.54) 2(-3.274,0) 3(-3.274,-2.54) 4(3.274,-2.54) 5(3.274,0) 6(3.274,2.54)
  silkscreen extent -2.92,-4.06 2.92,4.06, body extent -3.45,-3.94 3.45,3.94, height 2.85
CON_1053141204 [mm]
  rect 1.7x1.7 hole 1.2 mask+0.076: 1(0,0)
  round 1.7 hole 1.2 mask+0.076: 2(-2.5,0) 3(0,-2.5) 4(-2.5,-2.5)
  round 1.6 hole 1.6 unplated mask+0.076: 5(0,-9.68) 6(-2.5,-9.68)
  silkscreen extent -4.22,-12.88 3.5,0.64, body extent -4.24,-14.2 1.7,0.46, height 8.85
CONN_SMA-J-P-H-RA-TH1_SAI [mil]
  round 83 hole 63 mask+0: 1(0,0) 2(-100,100) 3(-100,-100) 4(100,-100) 5(100,100)
  silkscreen extent -143,-143 191,466, body extent -136,-137 140,457, height 372
CP_8_2_ADI [mm]
  rect 0.808x0.255 smd paste+0 mask+0.051: 1(-1.522,0.75) 2(-1.522,0.25) 3(-1.522,-0.25) 4(-1.522,-0.75) 5(1.522,-0.75) 6(1.522,-0.25) 7(1.522,0.25) 8(1.522,0.75)
  rect 1.6x1.88 smd paste+0 mask+0.051: 9(0,0)
  silkscreen extent -1.75,-1.75 1.75,1.75, body extent -1.63,-1.63 1.63,1.63, height 0.84
CP_56_1_ADI [mm]
  rect 0.808x0.255 smd paste+0 mask+0.051: 1(-3.896,3.25) 2(-3.896,2.75) 3(-3.896,2.25) 4(-3.896,1.75) 5(-3.896,1.25) 6(-3.896,0.75) 7(-3.896,0.25) 8(-3.896,-0.25) 9(-3.896,-0.75) 10(-3.896,-1.25) 11(-3.896,-1.75) 12(-3.896,-2.25) 13(-3.896,-2.75) 14(-3.896,-3.25) 29(3.896,-3.25) 30(3.896,-2.75) 31(3.896,-2.25) 32(3.896,-1.75) 33(3.896,-1.25) 34(3.896,-0.75) 35(3.896,-0.25) 36(3.896,0.25) 37(3.896,0.75) 38(3.896,1.25) 39(3.896,1.75) 40(3.896,2.25) 41(3.896,2.75) 42(3.896,3.25)
  rect 0.255x0.808 smd paste+0 mask+0.051: 15(-3.25,-3.896) 16(-2.75,-3.896) 17(-2.25,-3.896) 18(-1.75,-3.896) 19(-1.25,-3.896) 20(-0.75,-3.896) 21(-0.25,-3.896) 22(0.25,-3.896) 23(0.75,-3.896) 24(1.25,-3.896) 25(1.75,-3.896) 26(2.25,-3.896) 27(2.75,-3.896) 28(3.25,-3.896) 43(3.25,3.896) 44(2.75,3.896) 45(2.25,3.896) 46(1.75,3.896) 47(1.25,3.896) 48(0.75,3.896) 49(0.25,3.896) 50(-0.25,3.896) 51(-0.75,3.896) 52(-1.25,3.896) 53(-1.75,3.896) 54(-2.25,3.896) 55(-2.75,3.896) 56(-3.25,3.896)
  rect 6.248x6.248 smd paste-3.111 mask+0.051: 57(0,0)
  silkscreen extent -4.13,-4.13 4.13,4.13, body extent -4,-4 4,4, height 0.99
FB0603 [mm]
  rect 0.7x0.9 smd mask+0.051: 1(-0.7,0) 2(0.7,0)
  silkscreen extent -1.2,-0.6 1.2,0.6, body extent -0.76,-0.38 0.76,0.38, height 0.8
FIDUCIAL [mil]
  round 40 smd mask+20: 1(0,0)
  TOP_L1 pour cut-out: 43.31,0 43.31,4.27 41.64,12.63 38.38,20.51 33.64,27.61 27.61,33.64 20.51,38.38 12.63,41.64 4.27,43.31 0,43.31 -4.27,43.31 -12.63,41.64 -20.51,38.38 -27.61,33.64 -33.64,27.61 -38.38,20.51 -41.64,12.63 -43.31,4.27 -43.31,0 -43.31,-4.27 -41.64,-12.63 -38.38,-20.51 -33.64,-27.61 -27.61,-33.64 -20.51,-38.38 -12.63,-41.64 -4.27,-43.31 0,-43.31 4.27,-43.31 12.63,-41.64 20.51,-38.38 27.61,-33.64 33.64,-27.61 38.38,-20.51 41.64,-12.63 43.31,-4.27 43.31,0
HEADER_10X2 [mm]
  rect 1.7x1.7 hole 1.1 mask+0.05: 1(0,0)
  round 1.7 hole 1.1 mask+0.05: 2(0,2.54) 3(2.54,0) 4(2.54,2.54) 5(5.08,0) 6(5.08,2.54) 7(7.62,0) 8(7.62,2.54) 9(10.16,0) 10(10.16,2.54) 11(12.7,0) 12(12.7,2.54) 13(15.24,0) 14(15.24,2.54) 15(17.78,0) 16(17.78,2.54) 17(20.32,0) 18(20.32,2.54) 19(22.86,0) 20(22.86,2.54)
  silkscreen extent -1.27,-1.17 24.13,3.71, body extent -1.27,-1.27 24.13,3.81, height 7.75
"HOLE 3MM" [mm] "hole 3mm"
  round 4 hole 3.2: 1(0,0)
IND6X6_H3 [mm]
  rect 2.3x6.6 smd mask+0.051: 1(-2.15,0) 2(2.15,0)
  silkscreen extent -3.5,-3.56 3.5,3.5, body extent -3.1,-3.1 3.1,3.1, height 3.5
LED_0603_GREEN [mm] "LED 0603, Green"
  rect 0.7x0.9 smd mask+0.051: 1(-0.7,0) 2(0.7,0)
  silkscreen extent -1.14,-0.6 1.52,0.6, body extent -0.8,-0.4 0.8,0.4, height 0.7
MICTOR-38_PIN [mm]
  round 1.524 hole 2.43: 0(5.71,-3.495)
  rrect50% 0.43x1.6 smd mask+0.051: 1(0,0) 2(0,-6.99) 3(-0.635,0) 4(-0.635,-6.99) 5(-1.27,0) 6(-1.27,-6.99) 7(-1.905,0) 8(-1.905,-6.99) 9(-2.54,0) 10(-2.54,-6.99) 11(-3.175,0) 12(-3.175,-6.99) 13(-3.81,0) 14(-3.81,-6.99) 15(-4.445,0) 16(-4.445,-6.99) 17(-5.08,0) 18(-5.08,-6.99) 19(-5.715,0) 20(-5.715,-6.99) 21(-6.35,0) 22(-6.35,-6.99) 23(-6.985,0) 24(-6.985,-6.99) 25(-7.62,0) 26(-7.62,-6.99) 27(-8.255,0) 28(-8.255,-6.99) 29(-8.89,0) 30(-8.89,-6.99) 31(-9.525,0) 32(-9.525,-6.99) 33(-10.16,0) 34(-10.16,-6.99) 35(-10.795,0) 36(-10.795,-6.99) 37(-11.43,0) 38(-11.43,-6.99)
  round 1.2 hole 0.86: 39(-0.64,-3.495) 40(-3.18,-3.495) 41(-5.72,-3.495) 42(-8.26,-3.495) 43(-10.8,-3.495)
  silkscreen extent -18.8,-6.99 7.3,0, body extent -18.42,-7.85 6.98,0.86, height 6.05
NXP_74AVC4T245GU,115 [mm]
  rect 0.65x0.22 smd mask+0.051: 1(-0.725,0.6)
  rect 0.55x0.22 smd mask+0.051: 2(-0.775,0.2) 3(-0.775,-0.2) 4(-0.775,-0.6) 9(0.775,-0.6) 10(0.775,-0.2) 11(0.775,0.2) 12(0.775,0.6)
  rect 0.22x0.55 smd mask+0.051: 5(-0.6,-1.175) 6(-0.2,-1.175) 7(0.2,-1.175) 8(0.6,-1.175) 13(0.6,1.175) 14(0.2,1.175) 15(-0.2,1.175) 16(-0.6,1.175)
  silkscreen extent -1.05,-1.45 1.05,1.45, body extent -0.9,-1.3 0.9,1.3, height 0.5
PCIE_8LANE_EDGE [mil] "PCIE_8LANE_EDGE"
  rect 28x126 smd far side paste-100: A1(-984.25,-93.98)
  rect 28x169 smd far side paste-100: A2(-944.88,-115.48) A3(-905.51,-115.48) A4(-866.14,-115.48) A5(-826.77,-115.48) A6(-787.4,-115.48) A7(-748.03,-115.48) A8(-708.66,-115.48) A9(-669.29,-115.48) A10(-629.92,-115.48) A11(-590.55,-115.48) A12(-472.44,-115.48) A13(-433.07,-115.48) A14(-393.7,-115.48) A15(-354.33,-115.48) A16(-314.96,-115.48) A17(-275.59,-115.48) A18(-236.22,-115.48) A19(-196.85,-115.48) A20(-157.48,-115.48) A21(-118.11,-115.48) A22(-78.74,-115.48) A23(-39.37,-115.48) A24(0,-115.48) A25(39.37,-115.48) A26(78.74,-115.48) A27(118.11,-115.48) A28(157.48,-115.48) A29(196.85,-115.48) A30(236.22,-115.48) A31(275.59,-115.48) A32(314.96,-115.48)
  rect 28x169 smd paste-100 mask+2: B1(-984.25,-115.48) B2(-944.88,-115.48) B3(-905.51,-115.48) B4(-866.14,-115.48) B5(-826.77,-115.48) B6(-787.4,-115.48) B7(-748.03,-115.48) B8(-708.66,-115.48) B9(-669.29,-115.48) B10(-629.92,-115.48) B11(-590.55,-115.48) B12(-472.44,-115.48) B13(-433.07,-115.48) B14(-393.7,-115.48) B15(-354.33,-115.48) B16(-314.96,-115.48) B18(-236.22,-115.48) B19(-196.85,-115.48) B20(-157.48,-115.48) B21(-118.11,-115.48) B22(-78.74,-115.48) B23(-39.37,-115.48) B24(0,-115.48) B25(39.37,-115.48) B26(78.74,-115.48) B27(118.11,-115.48) B28(157.48,-115.48) B29(196.85,-115.48) B30(236.22,-115.48) B32(314.96,-115.48)
  rect 28x126 smd paste-100 mask+2: B17(-275.59,-93.98) B31(275.59,-93.98)
R0402 [mil] "R0402"
  rect 25x25 smd mask+2: 1(-18.5,0) 2(20.9,0)
  silkscreen extent -36,-17 40,17, body extent -20,-10 20,10, height 14
r0402 [mil] "R0402"
  rect 25x25 smd mask+2: 1(-18.5,0) 2(20.9,0)
  silkscreen extent -36,-17 40,17, body extent -20,-10 20,10, height 14
R0805 [mil] "R0805"
  rect 60x50 smd mask+2: 1(-45,0) 2(45,0)
  silkscreen extent -80,-30 80,30, body extent -39,-25 39,24, height 31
